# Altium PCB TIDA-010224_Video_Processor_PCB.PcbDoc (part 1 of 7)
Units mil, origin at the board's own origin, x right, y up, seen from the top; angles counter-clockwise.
Board outline 2355.46 x 4164 mil, 10 copper layers (L1-Top Layer, L2-GND, L3-SIG1, L4-GND, L5-PWR, L6-PWR, L7-GND, L8-SIG2, L9-GND, L10-Bottom Layer), stack 62.2 mil thick; 508 components, 274 nets, 3619 pads, 705 vias.
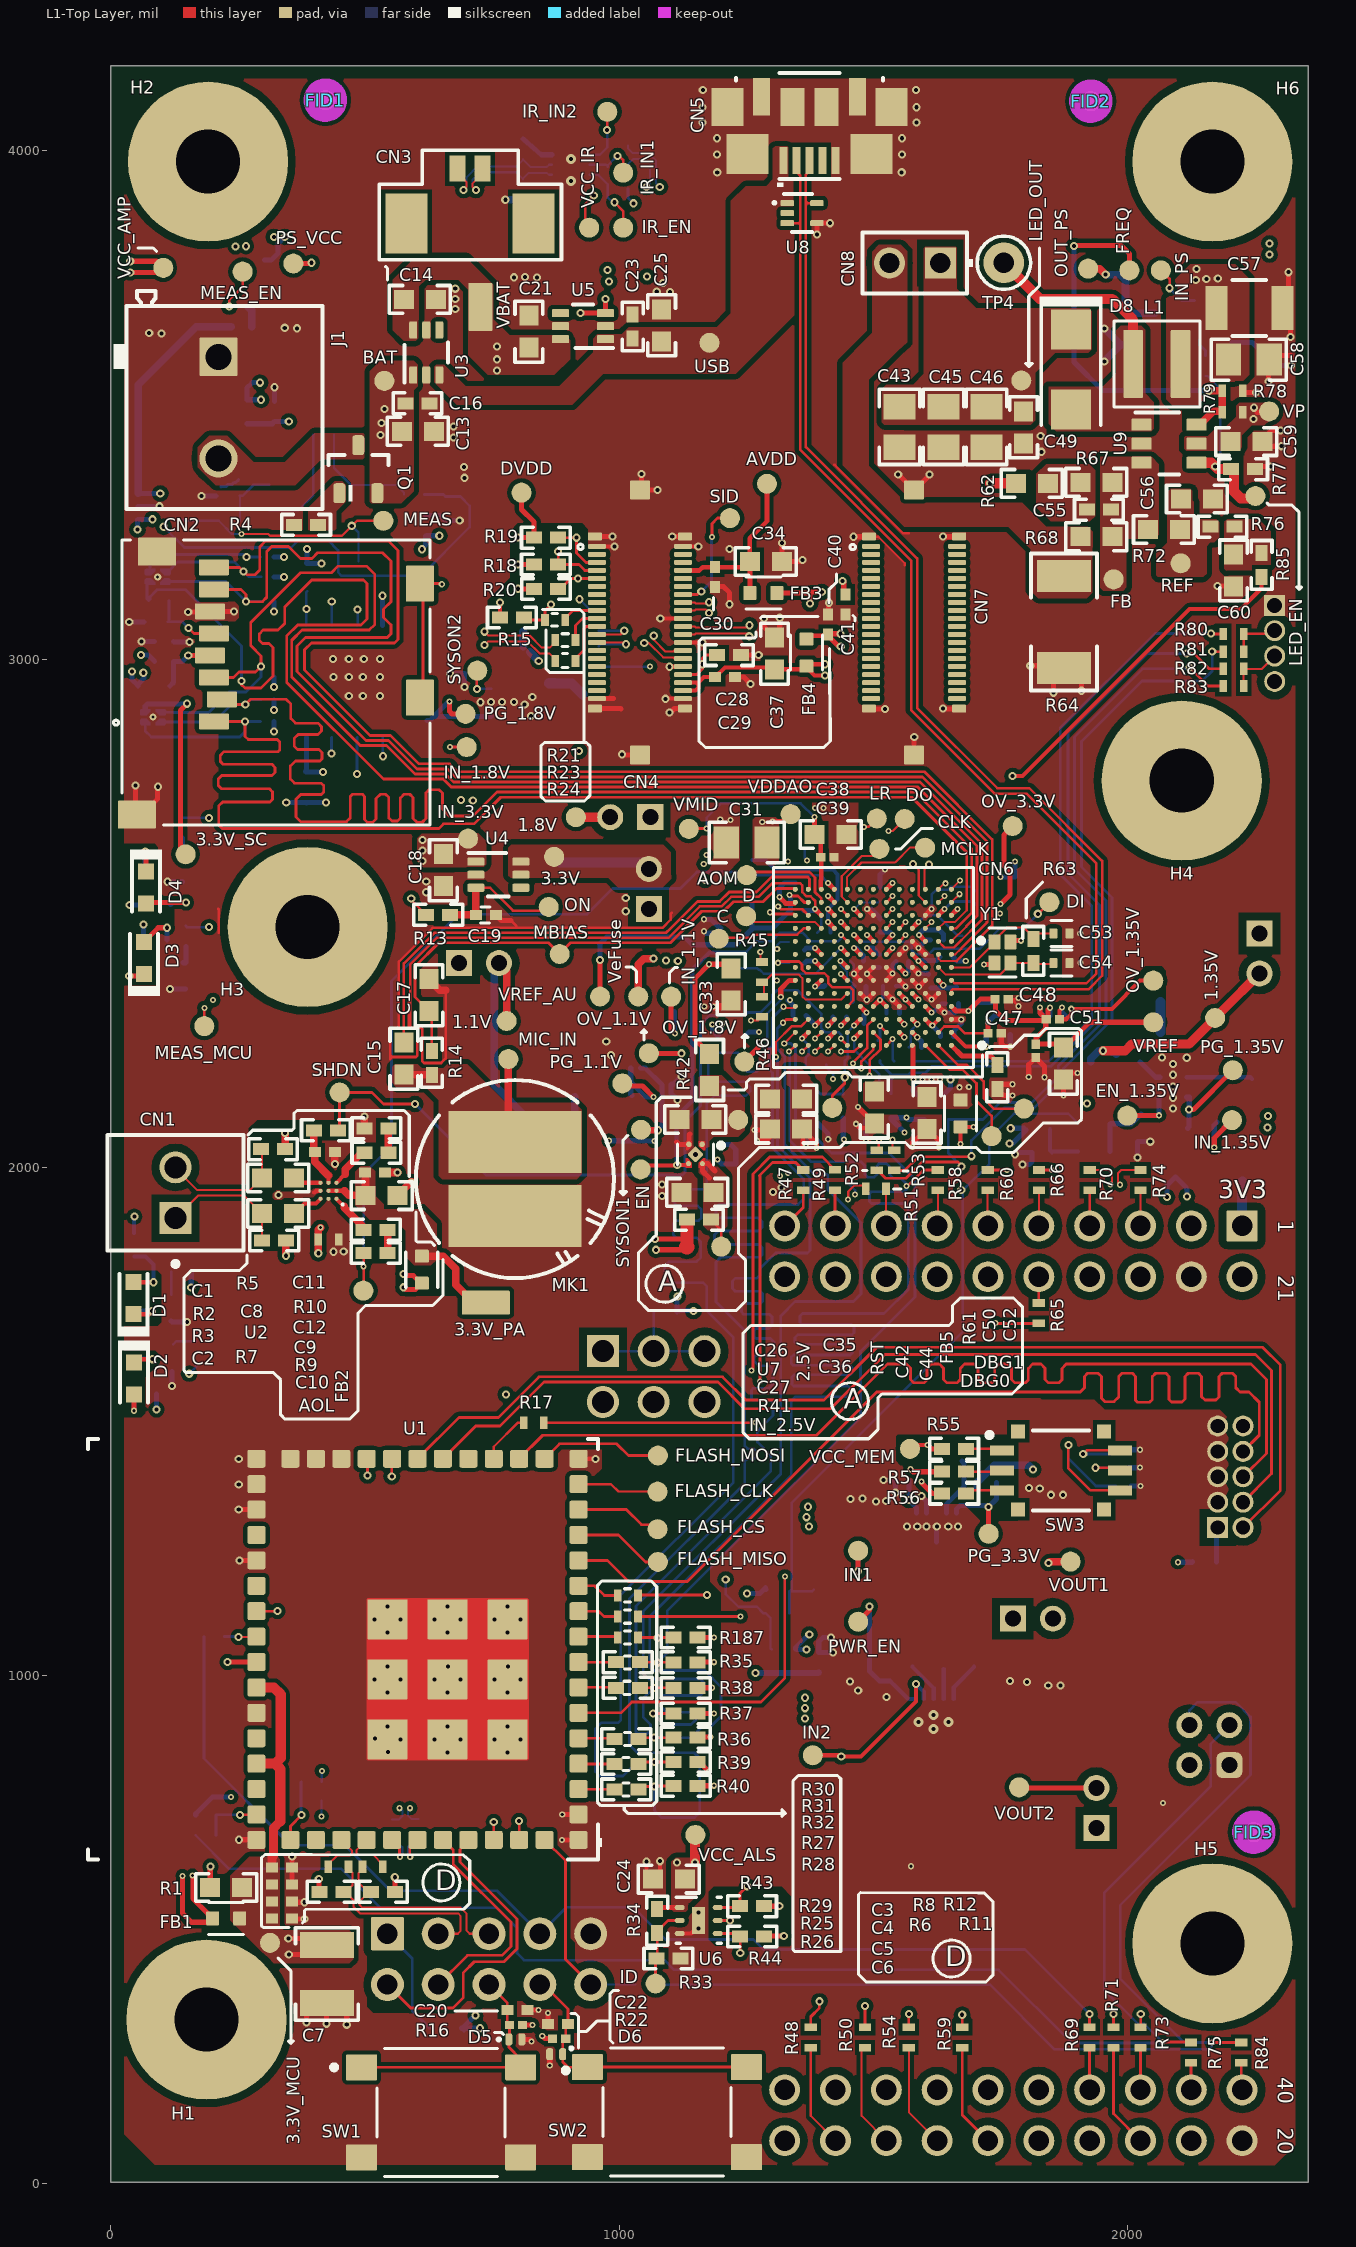
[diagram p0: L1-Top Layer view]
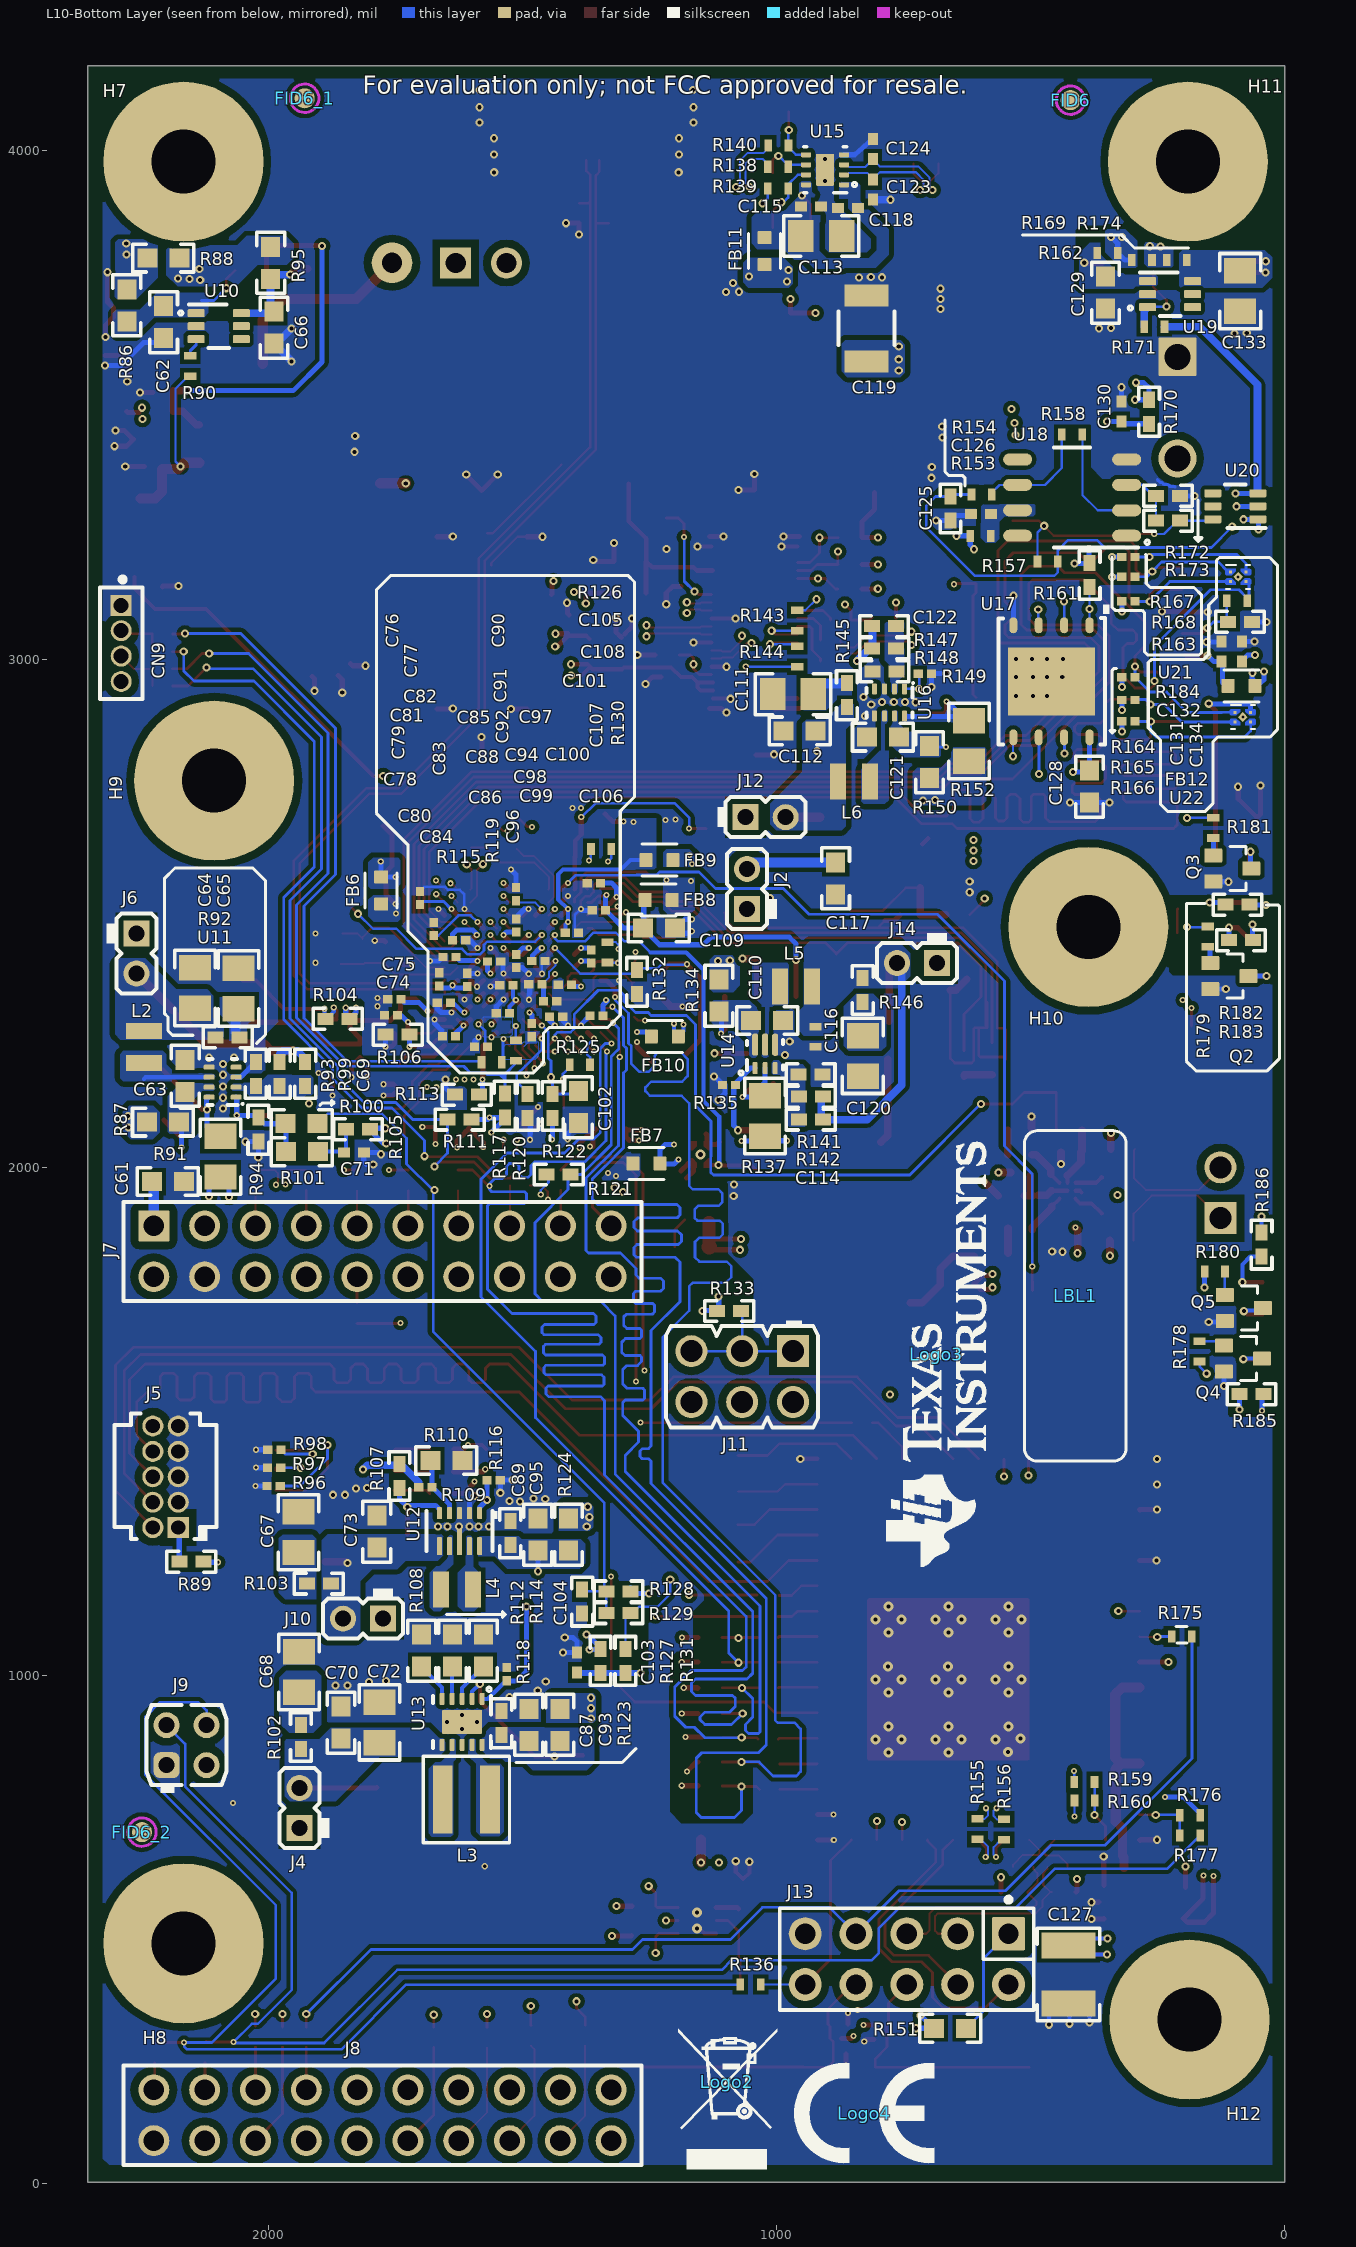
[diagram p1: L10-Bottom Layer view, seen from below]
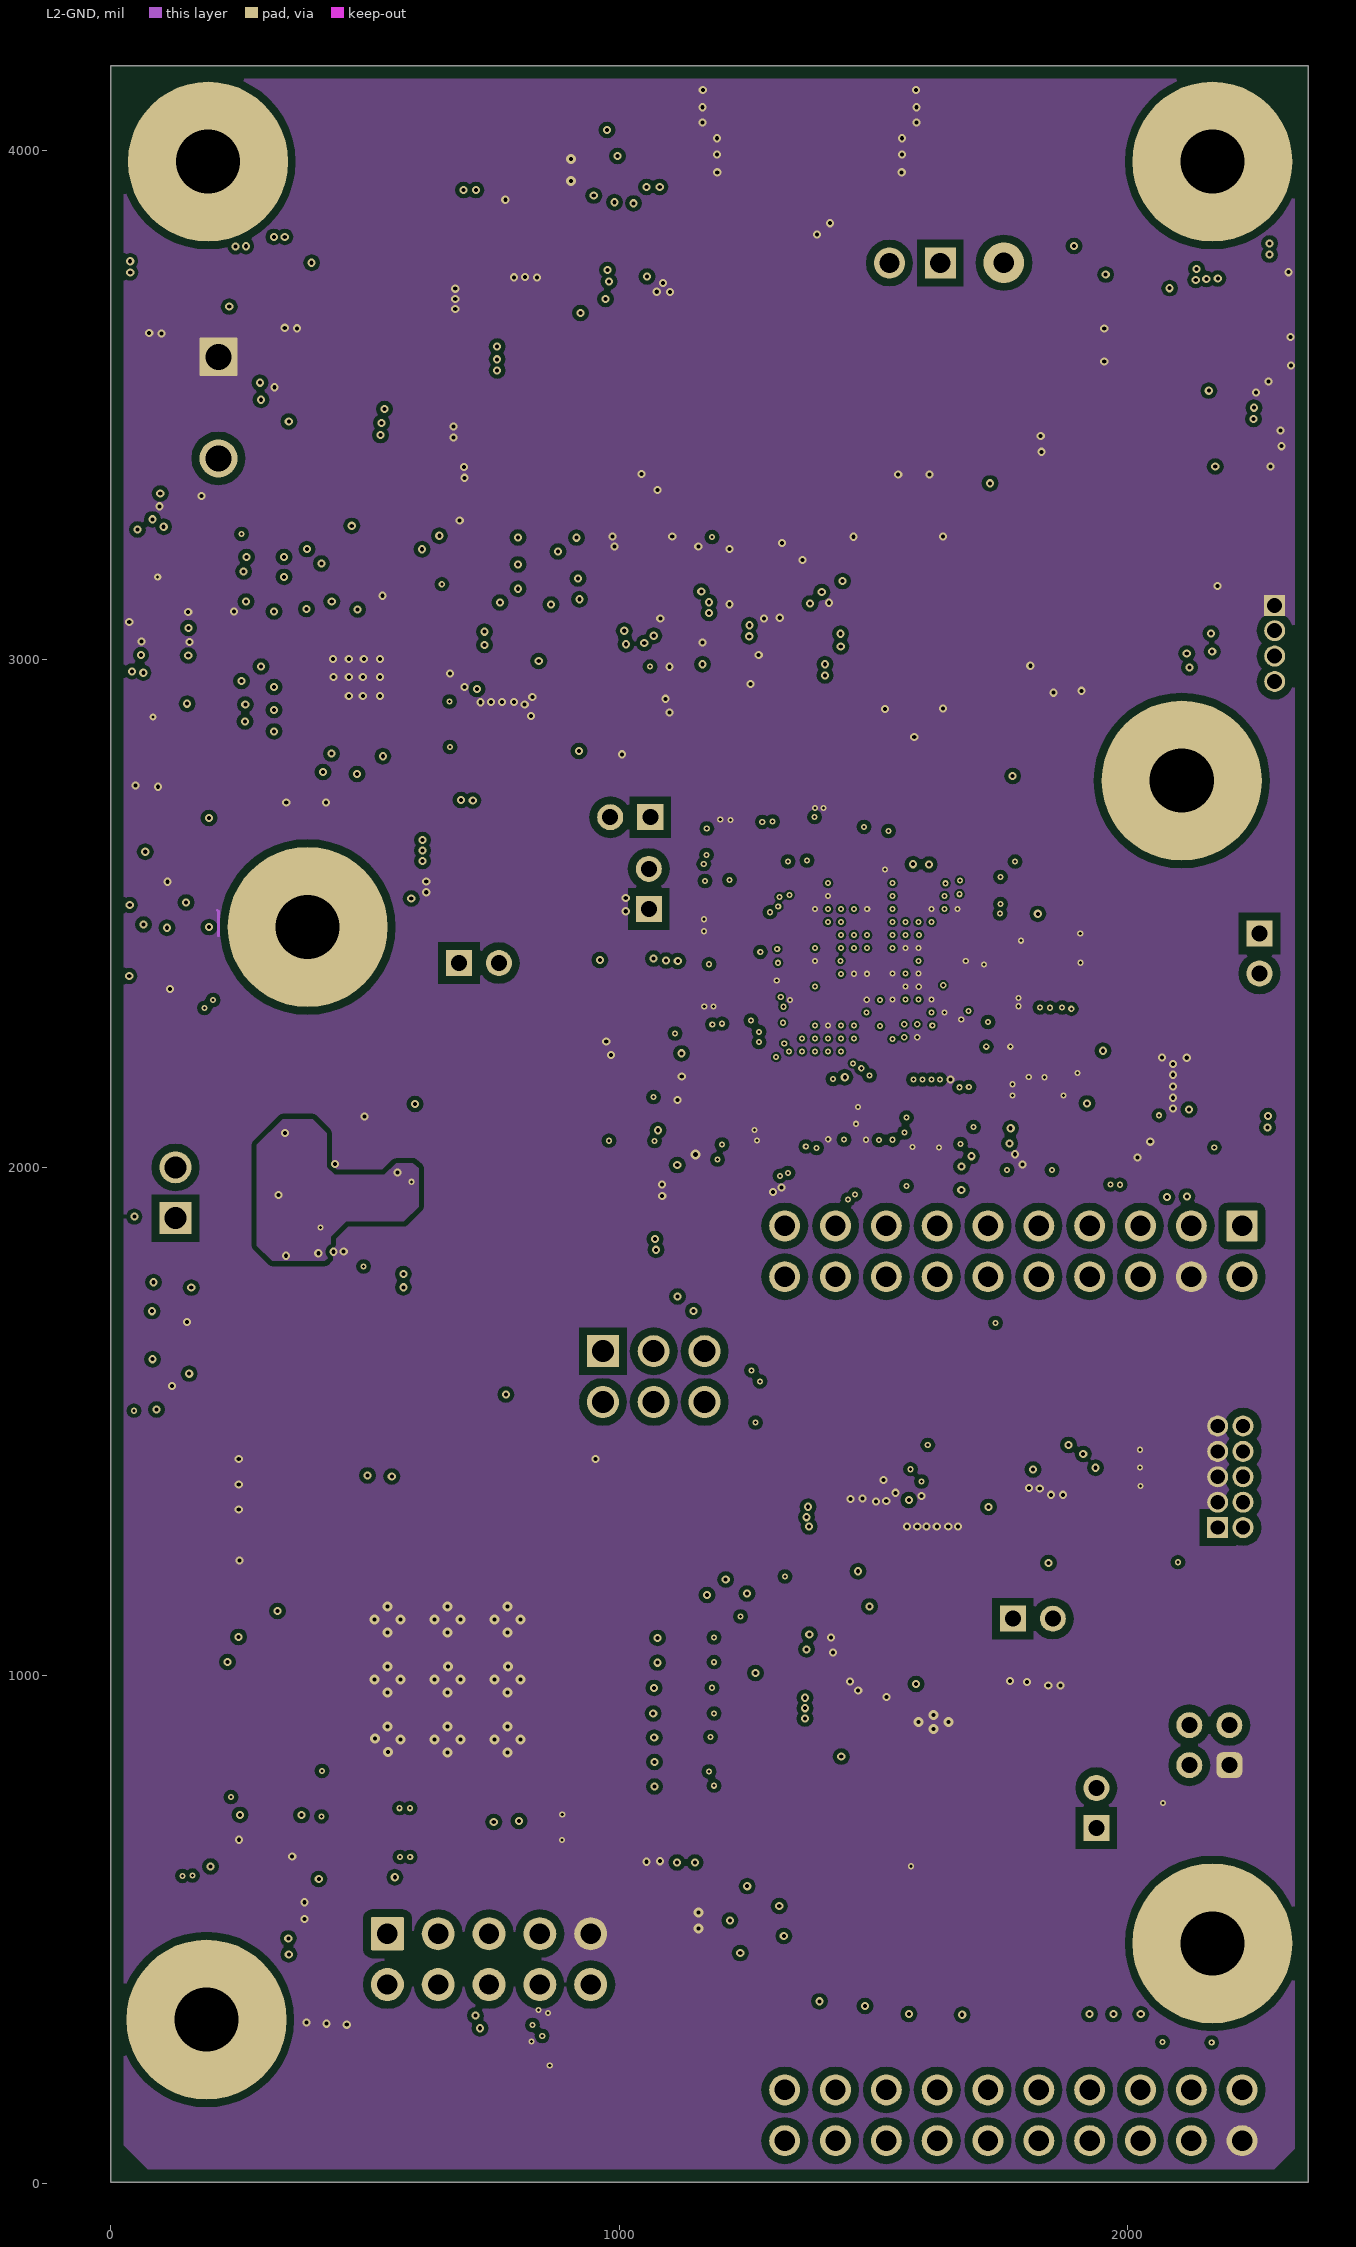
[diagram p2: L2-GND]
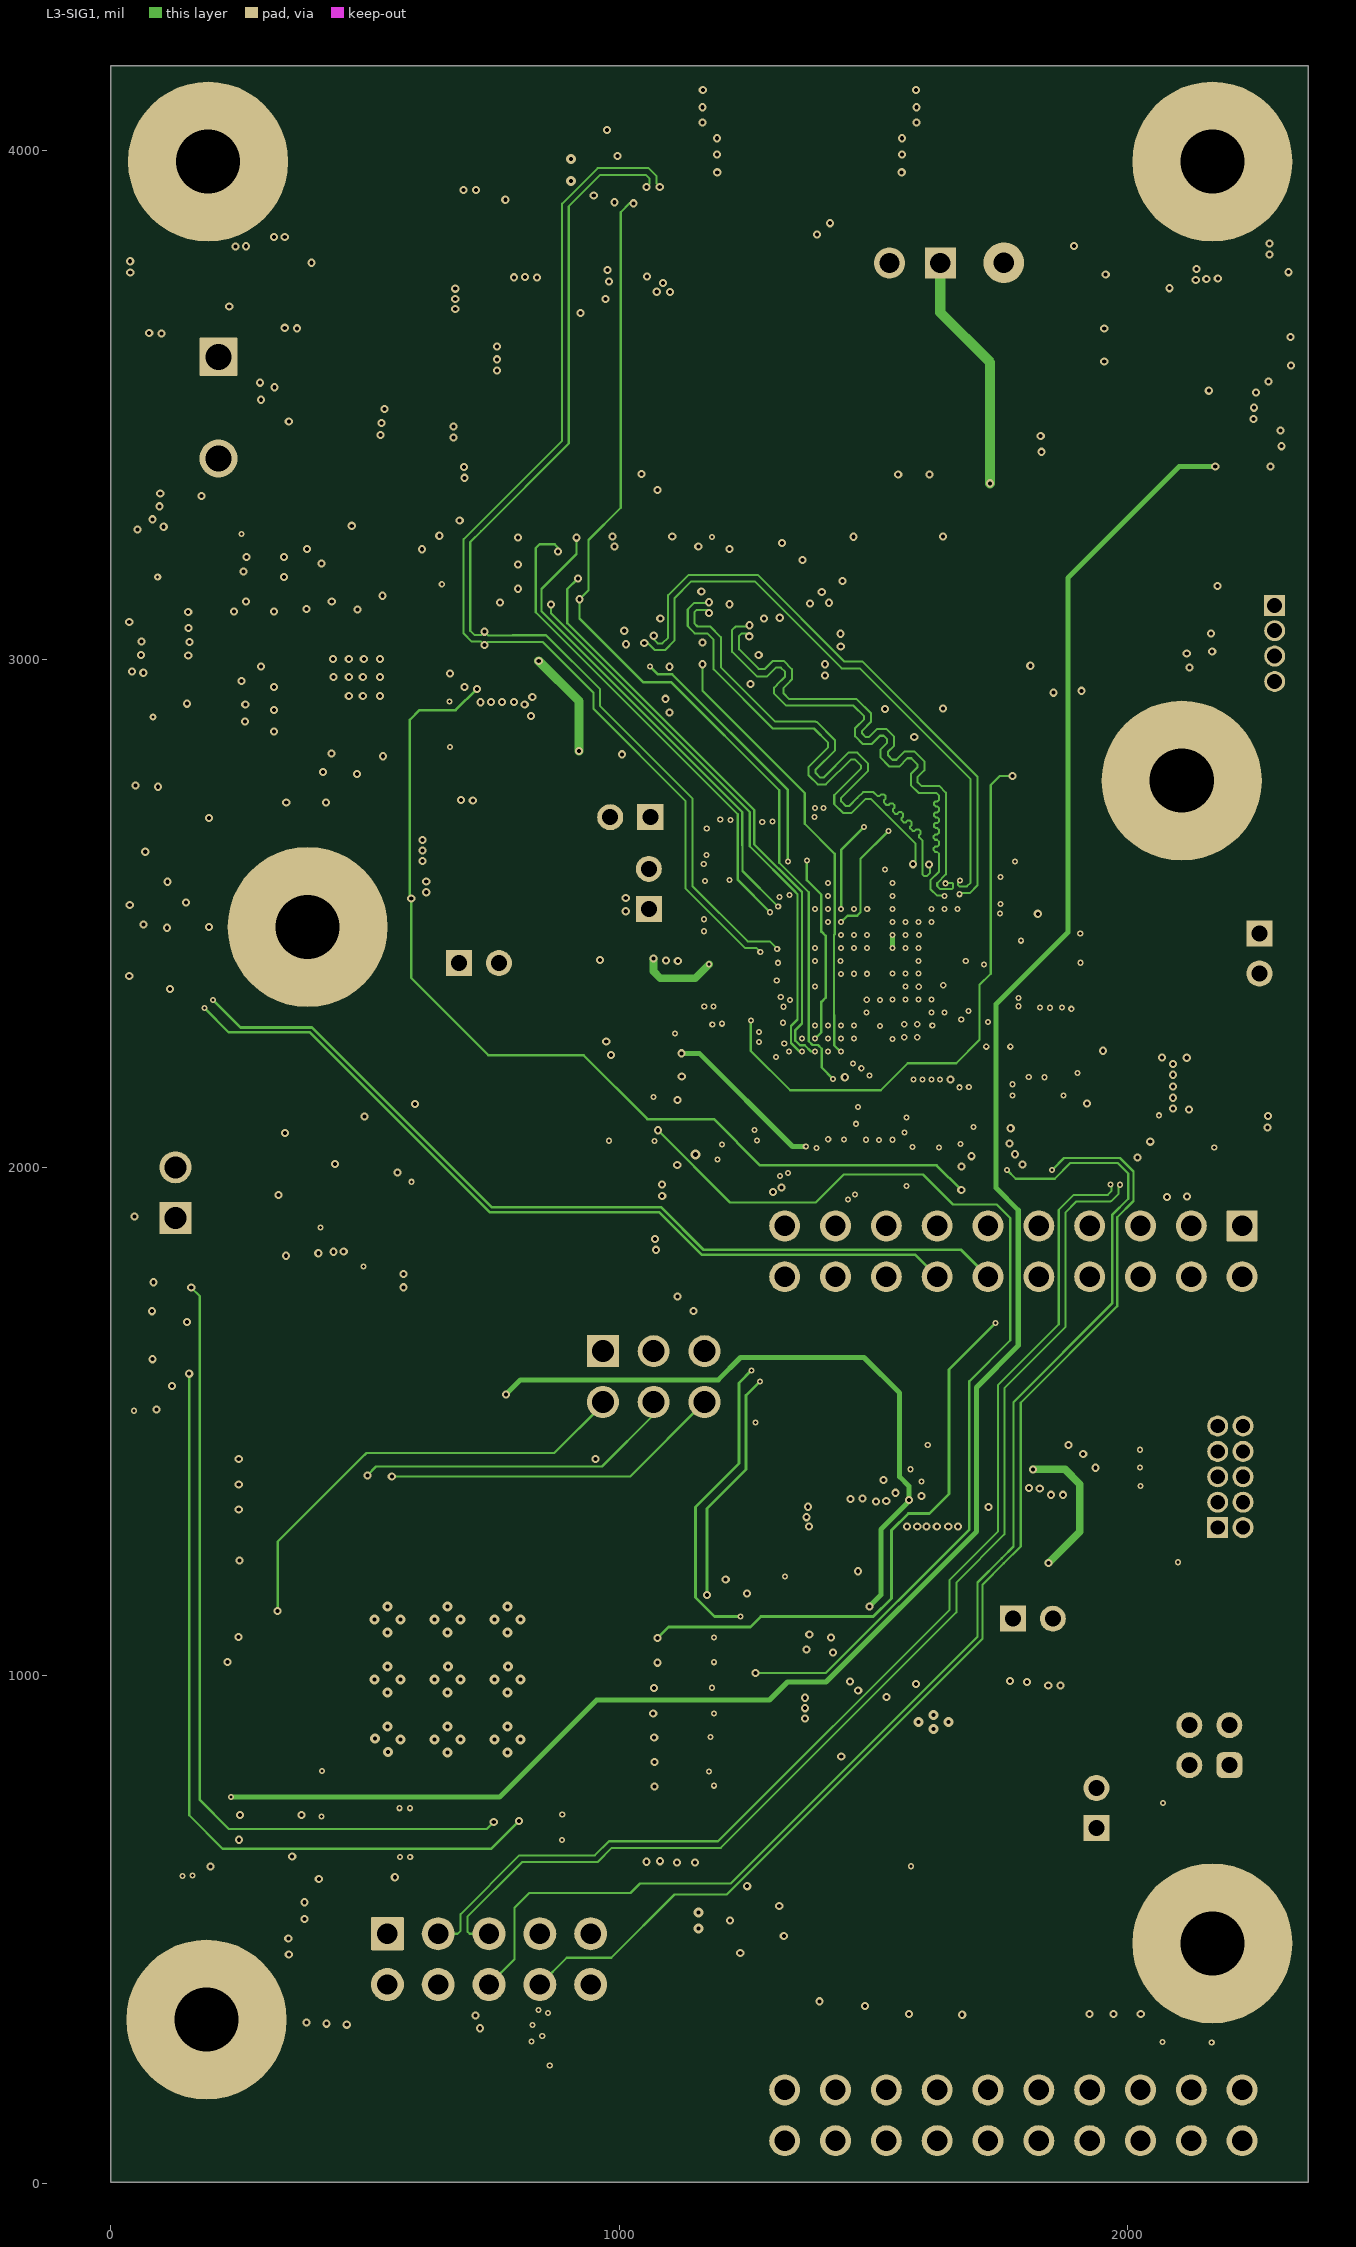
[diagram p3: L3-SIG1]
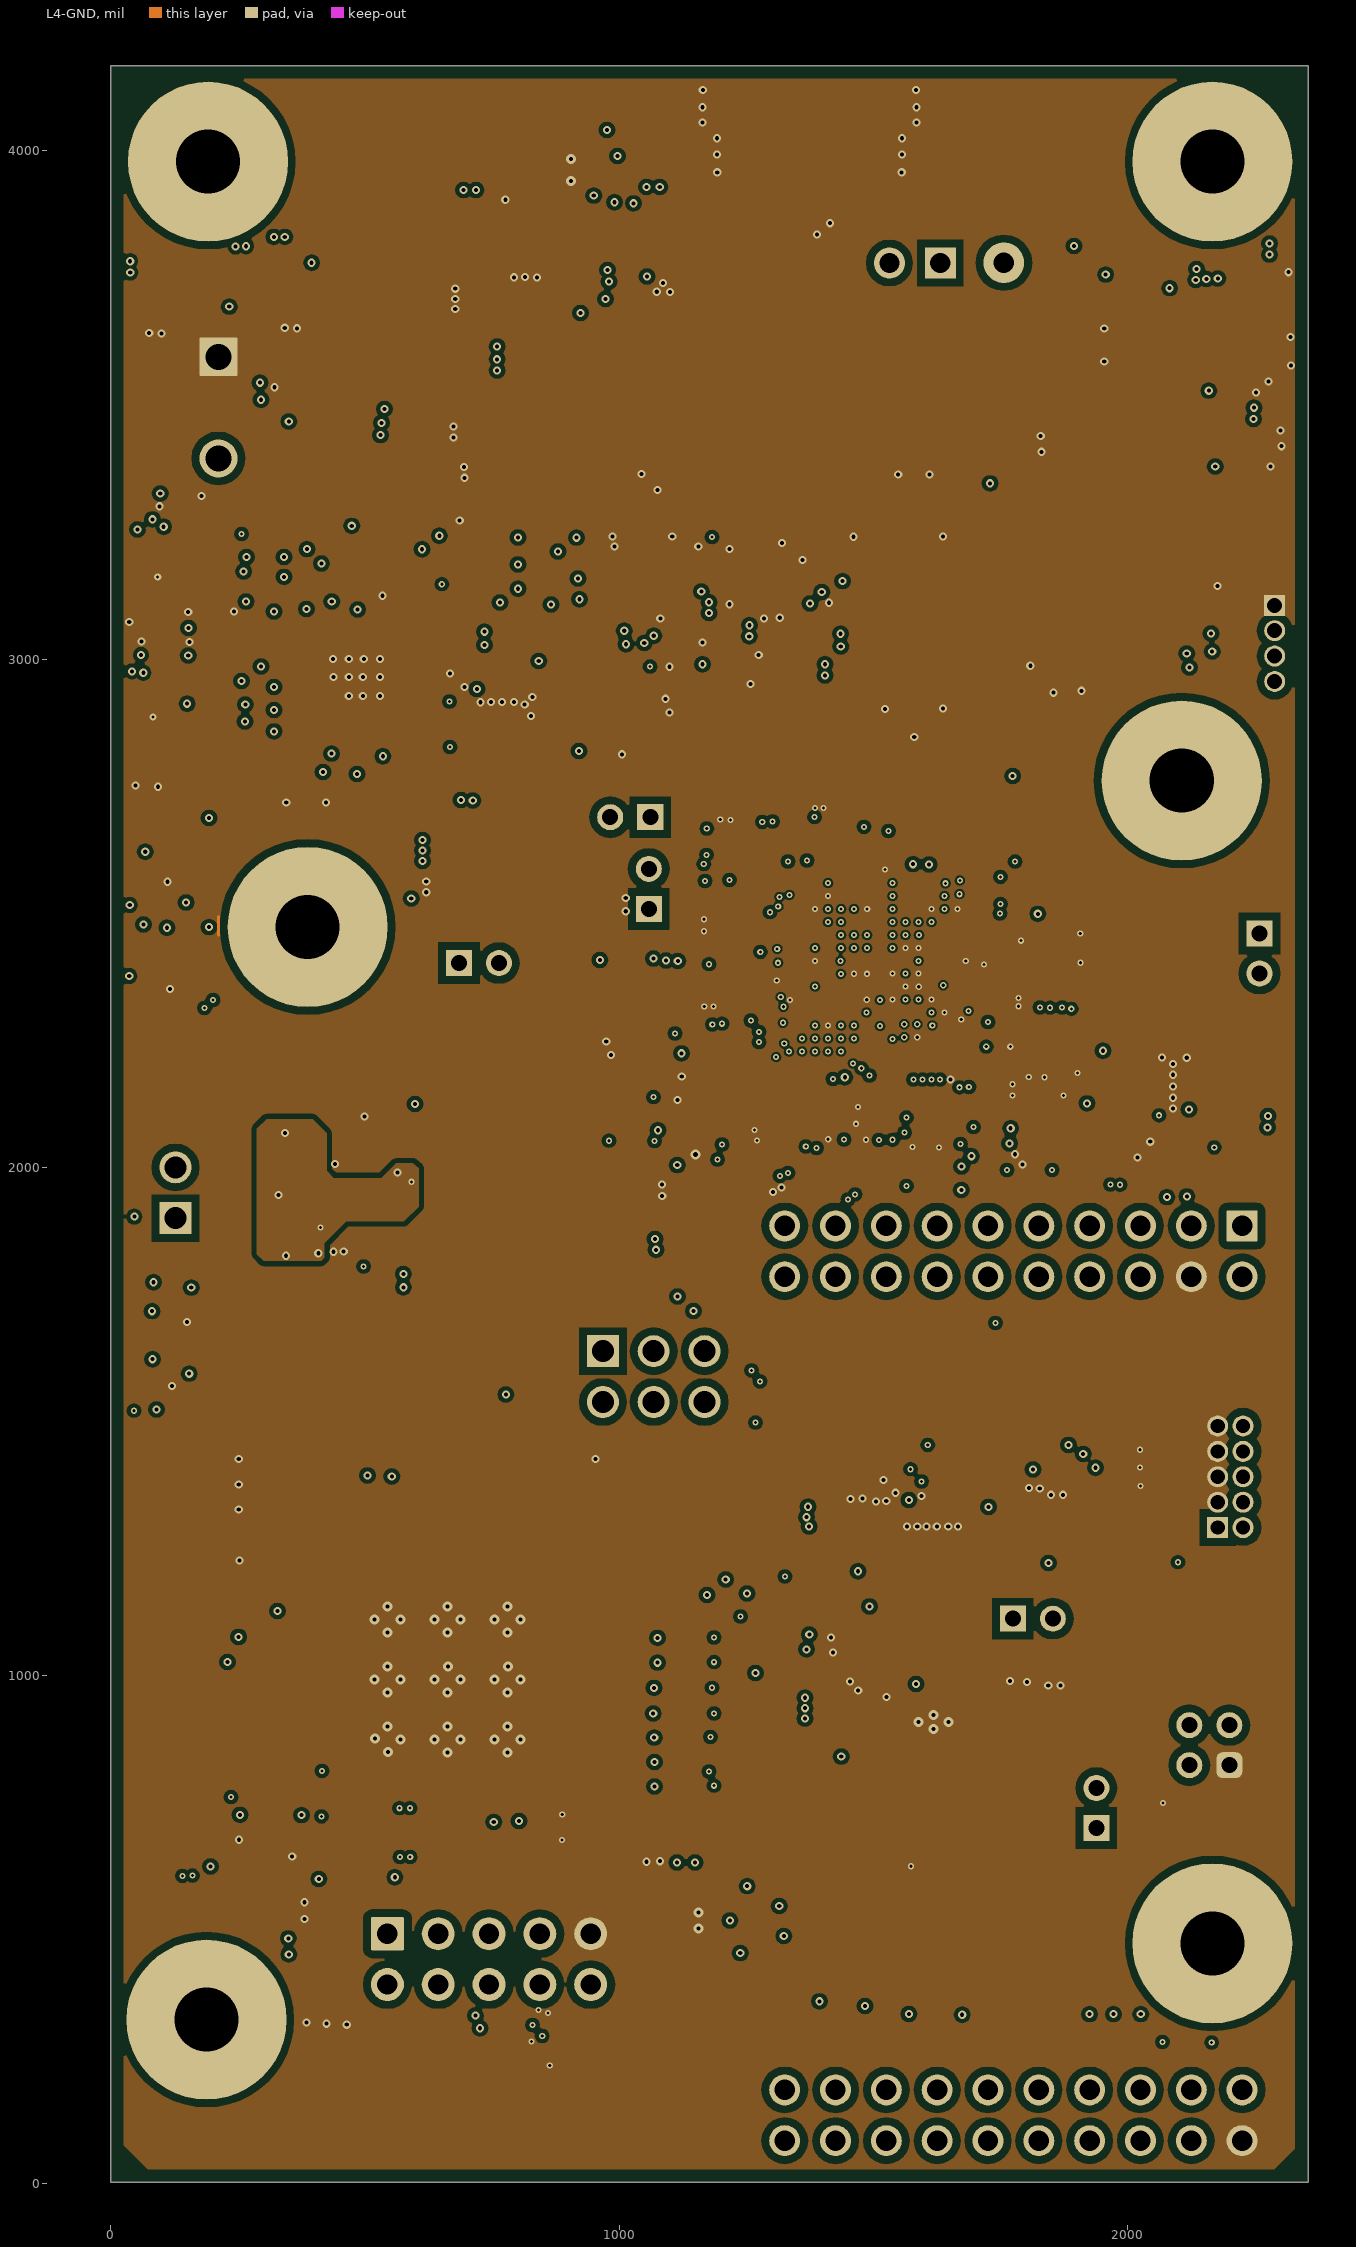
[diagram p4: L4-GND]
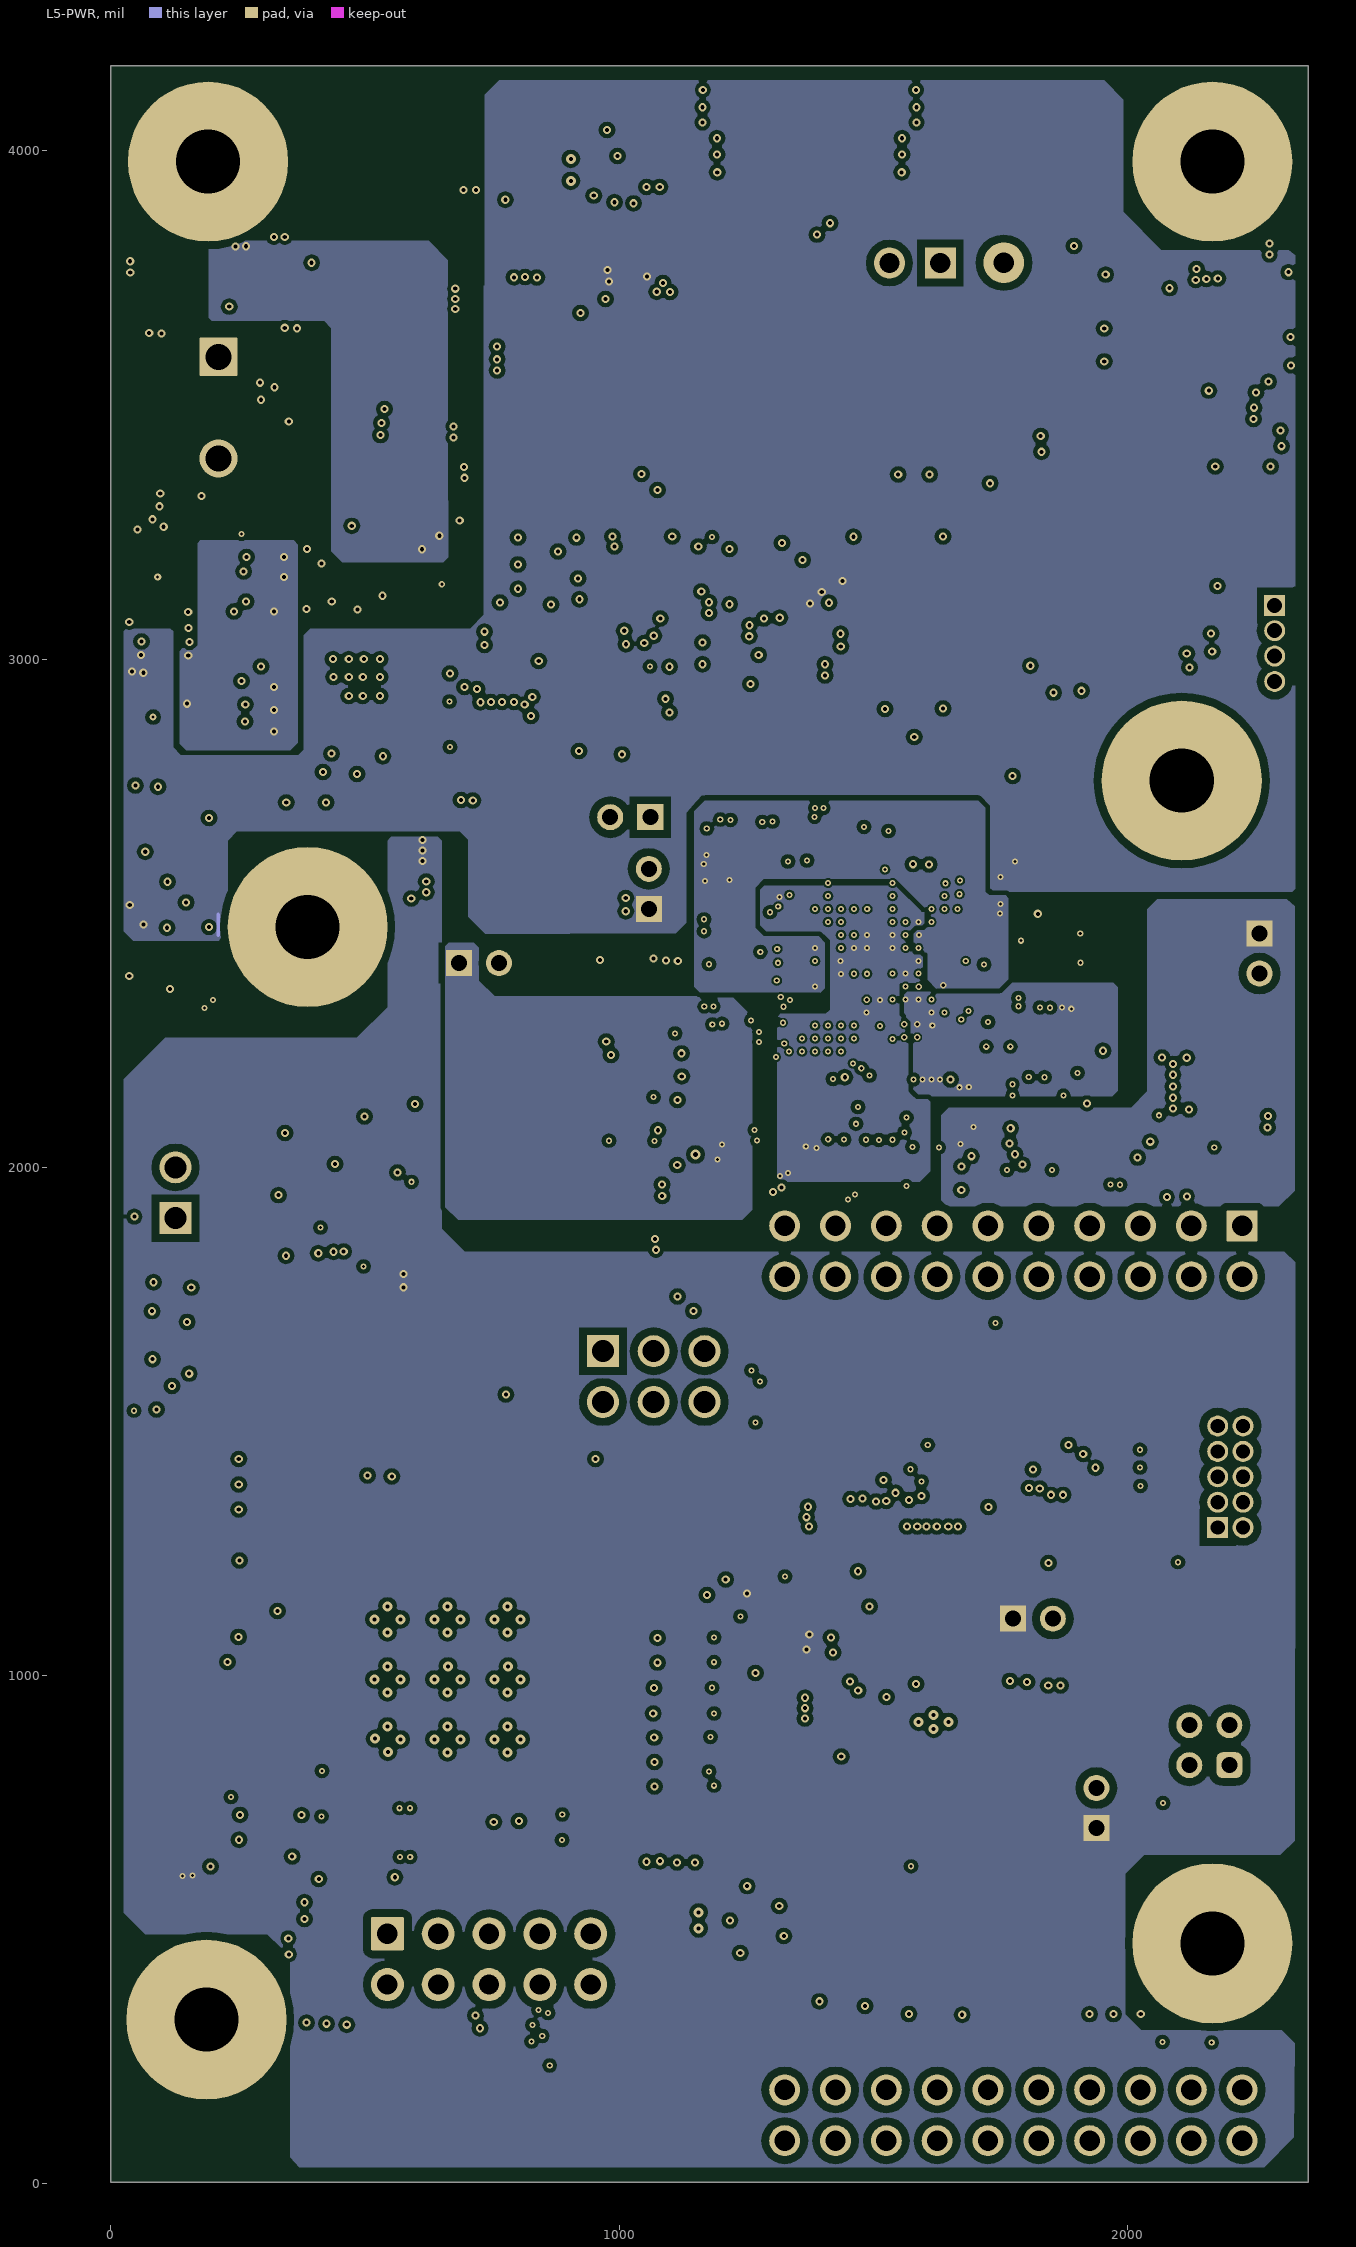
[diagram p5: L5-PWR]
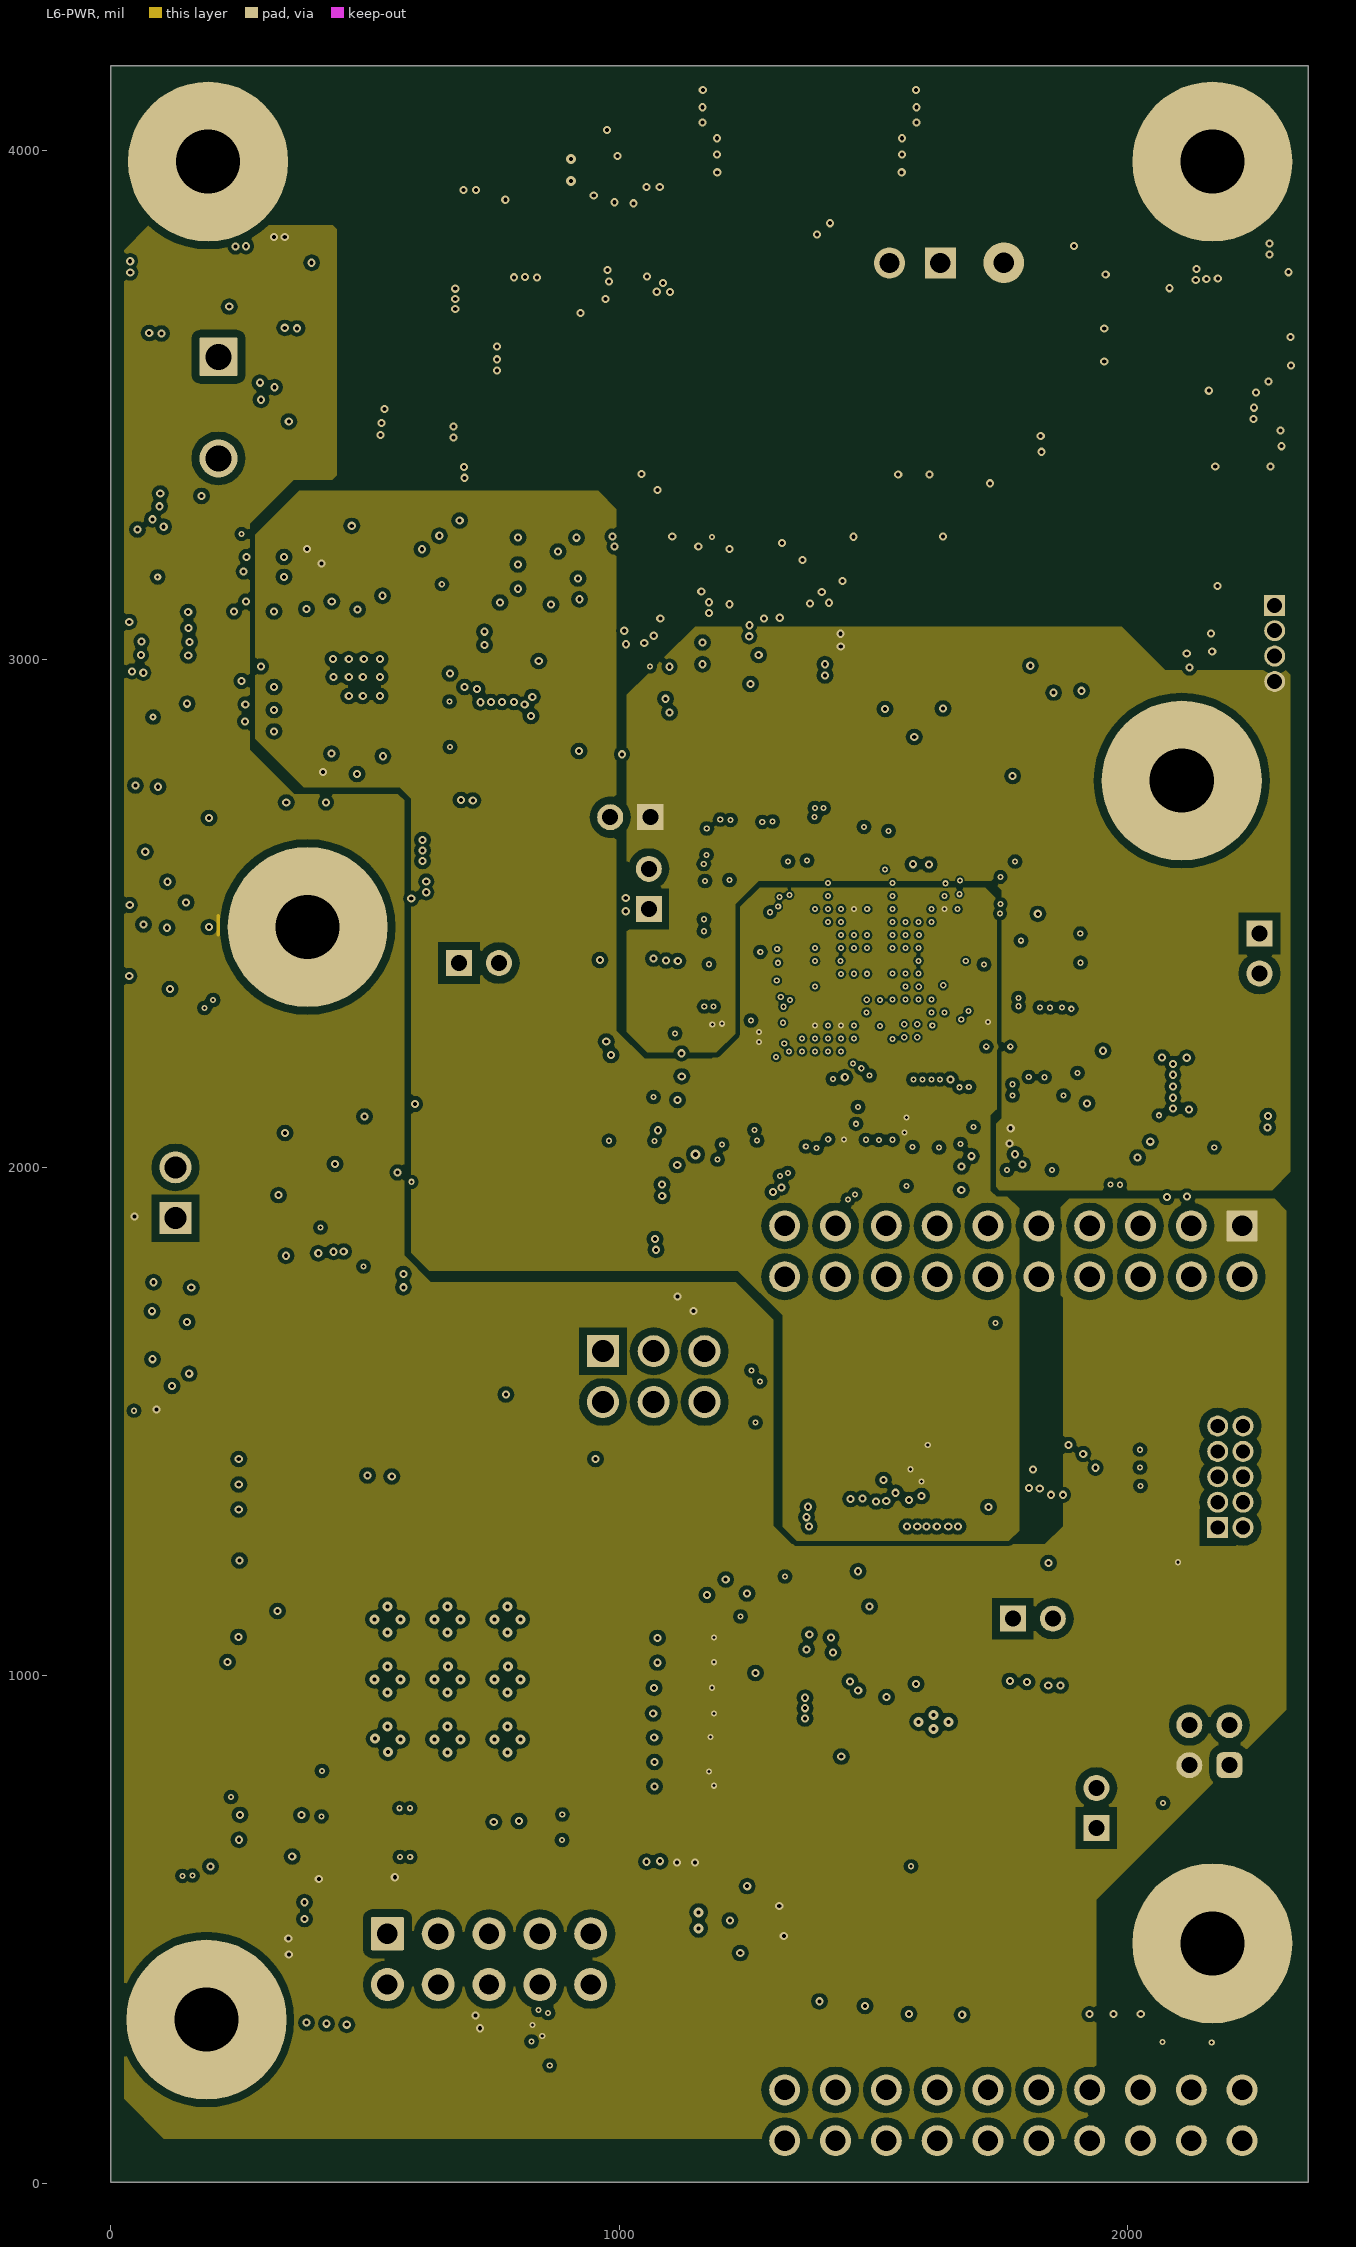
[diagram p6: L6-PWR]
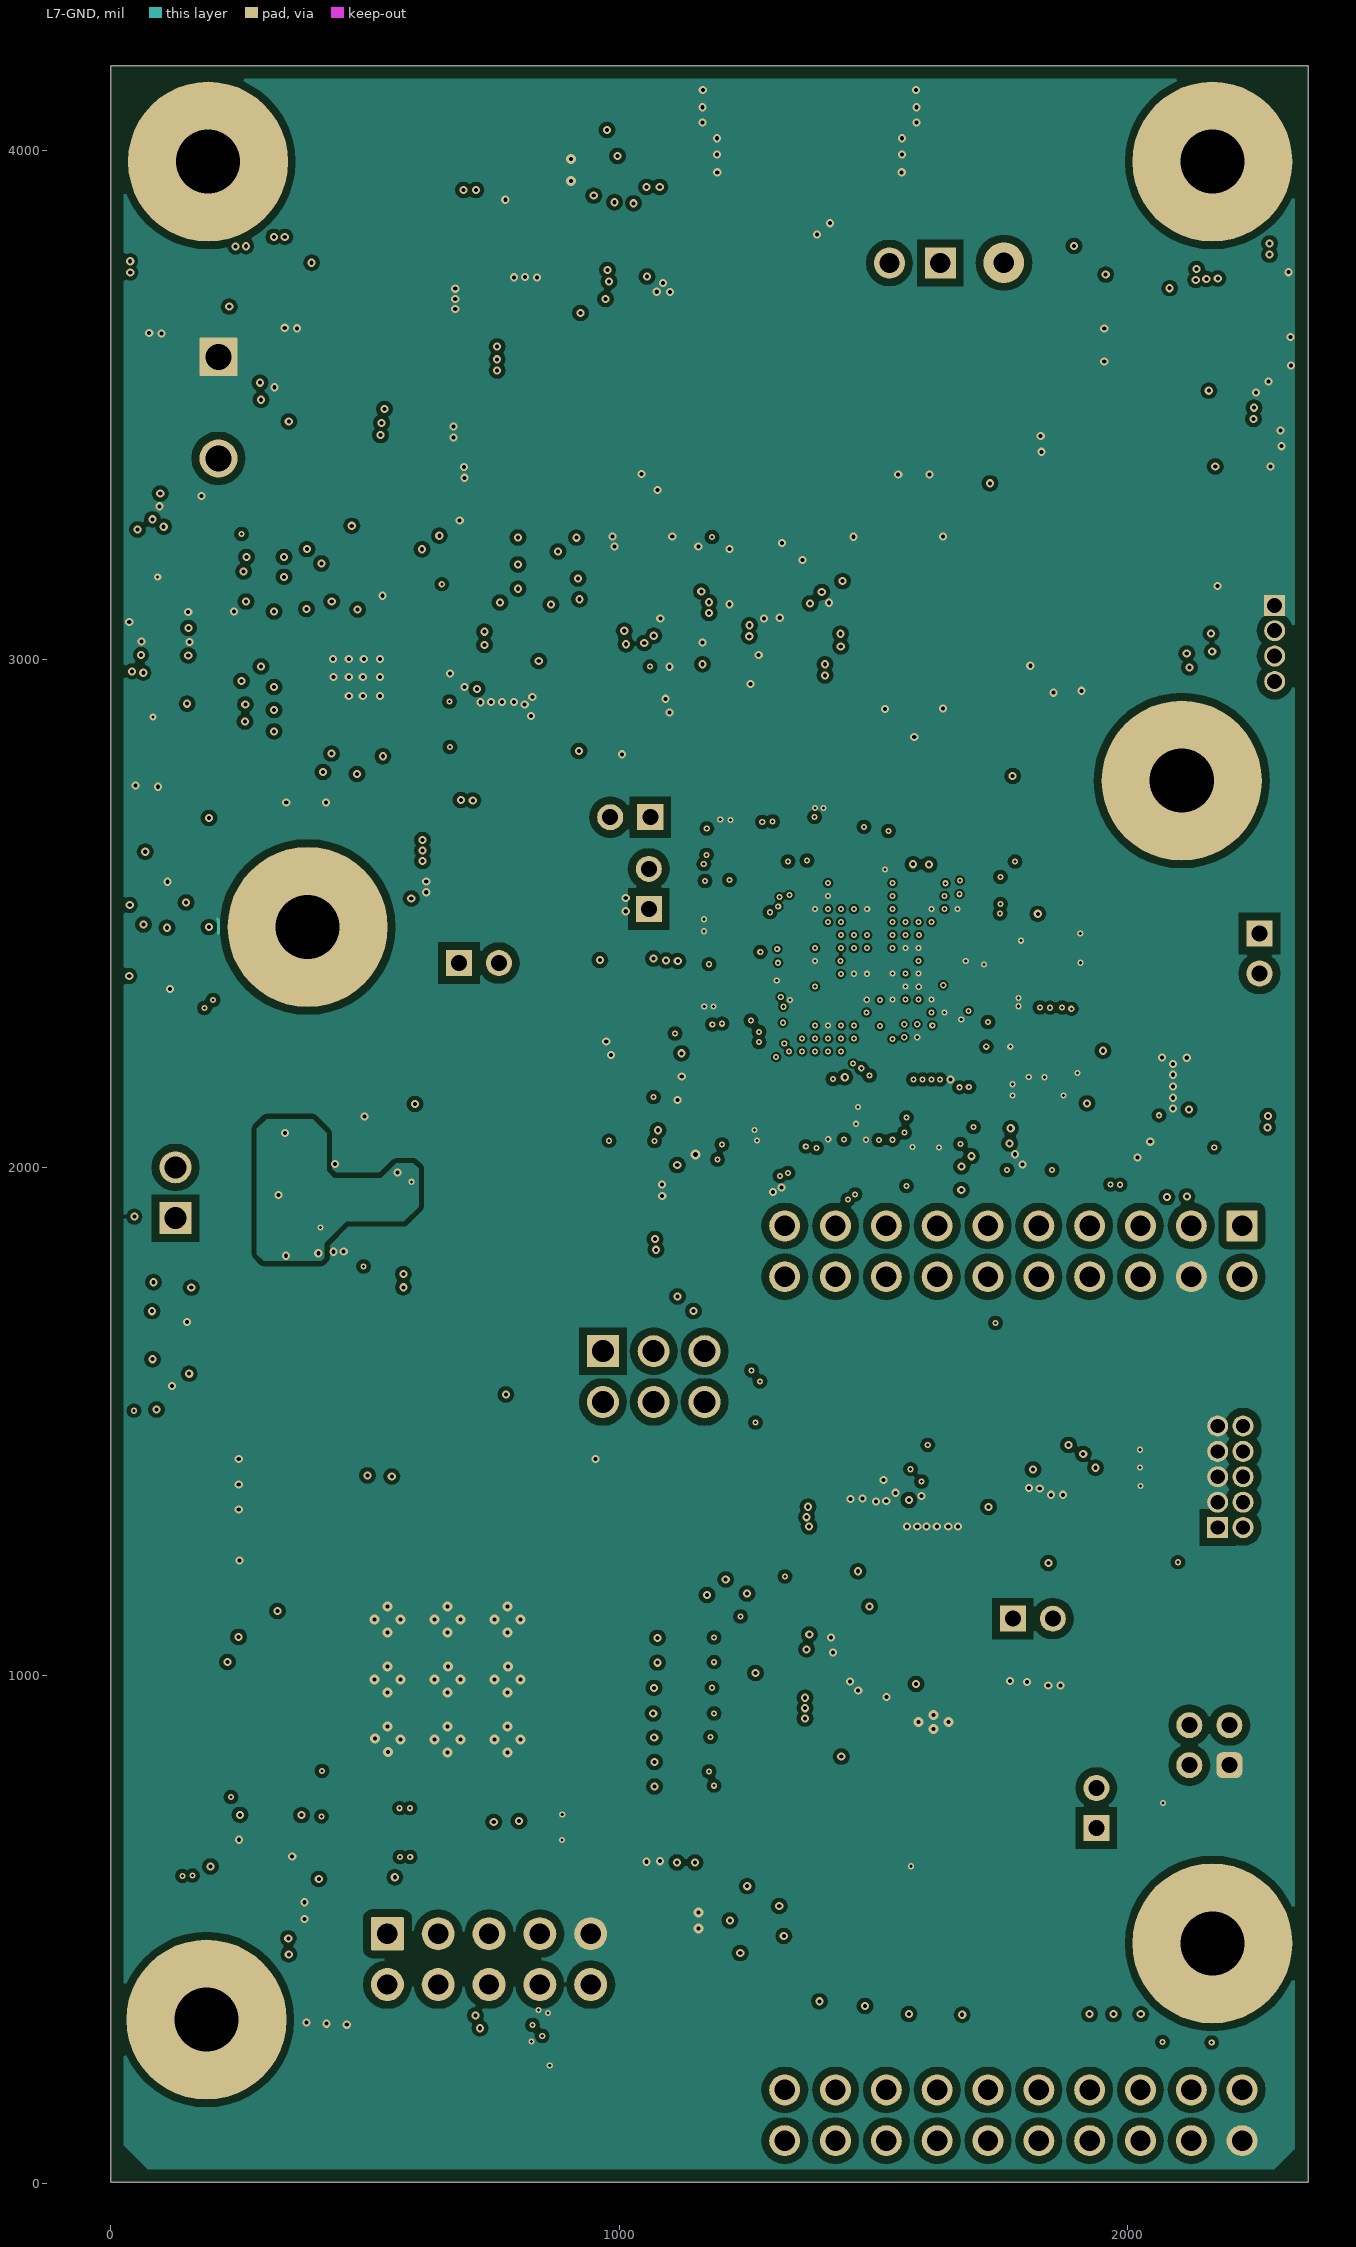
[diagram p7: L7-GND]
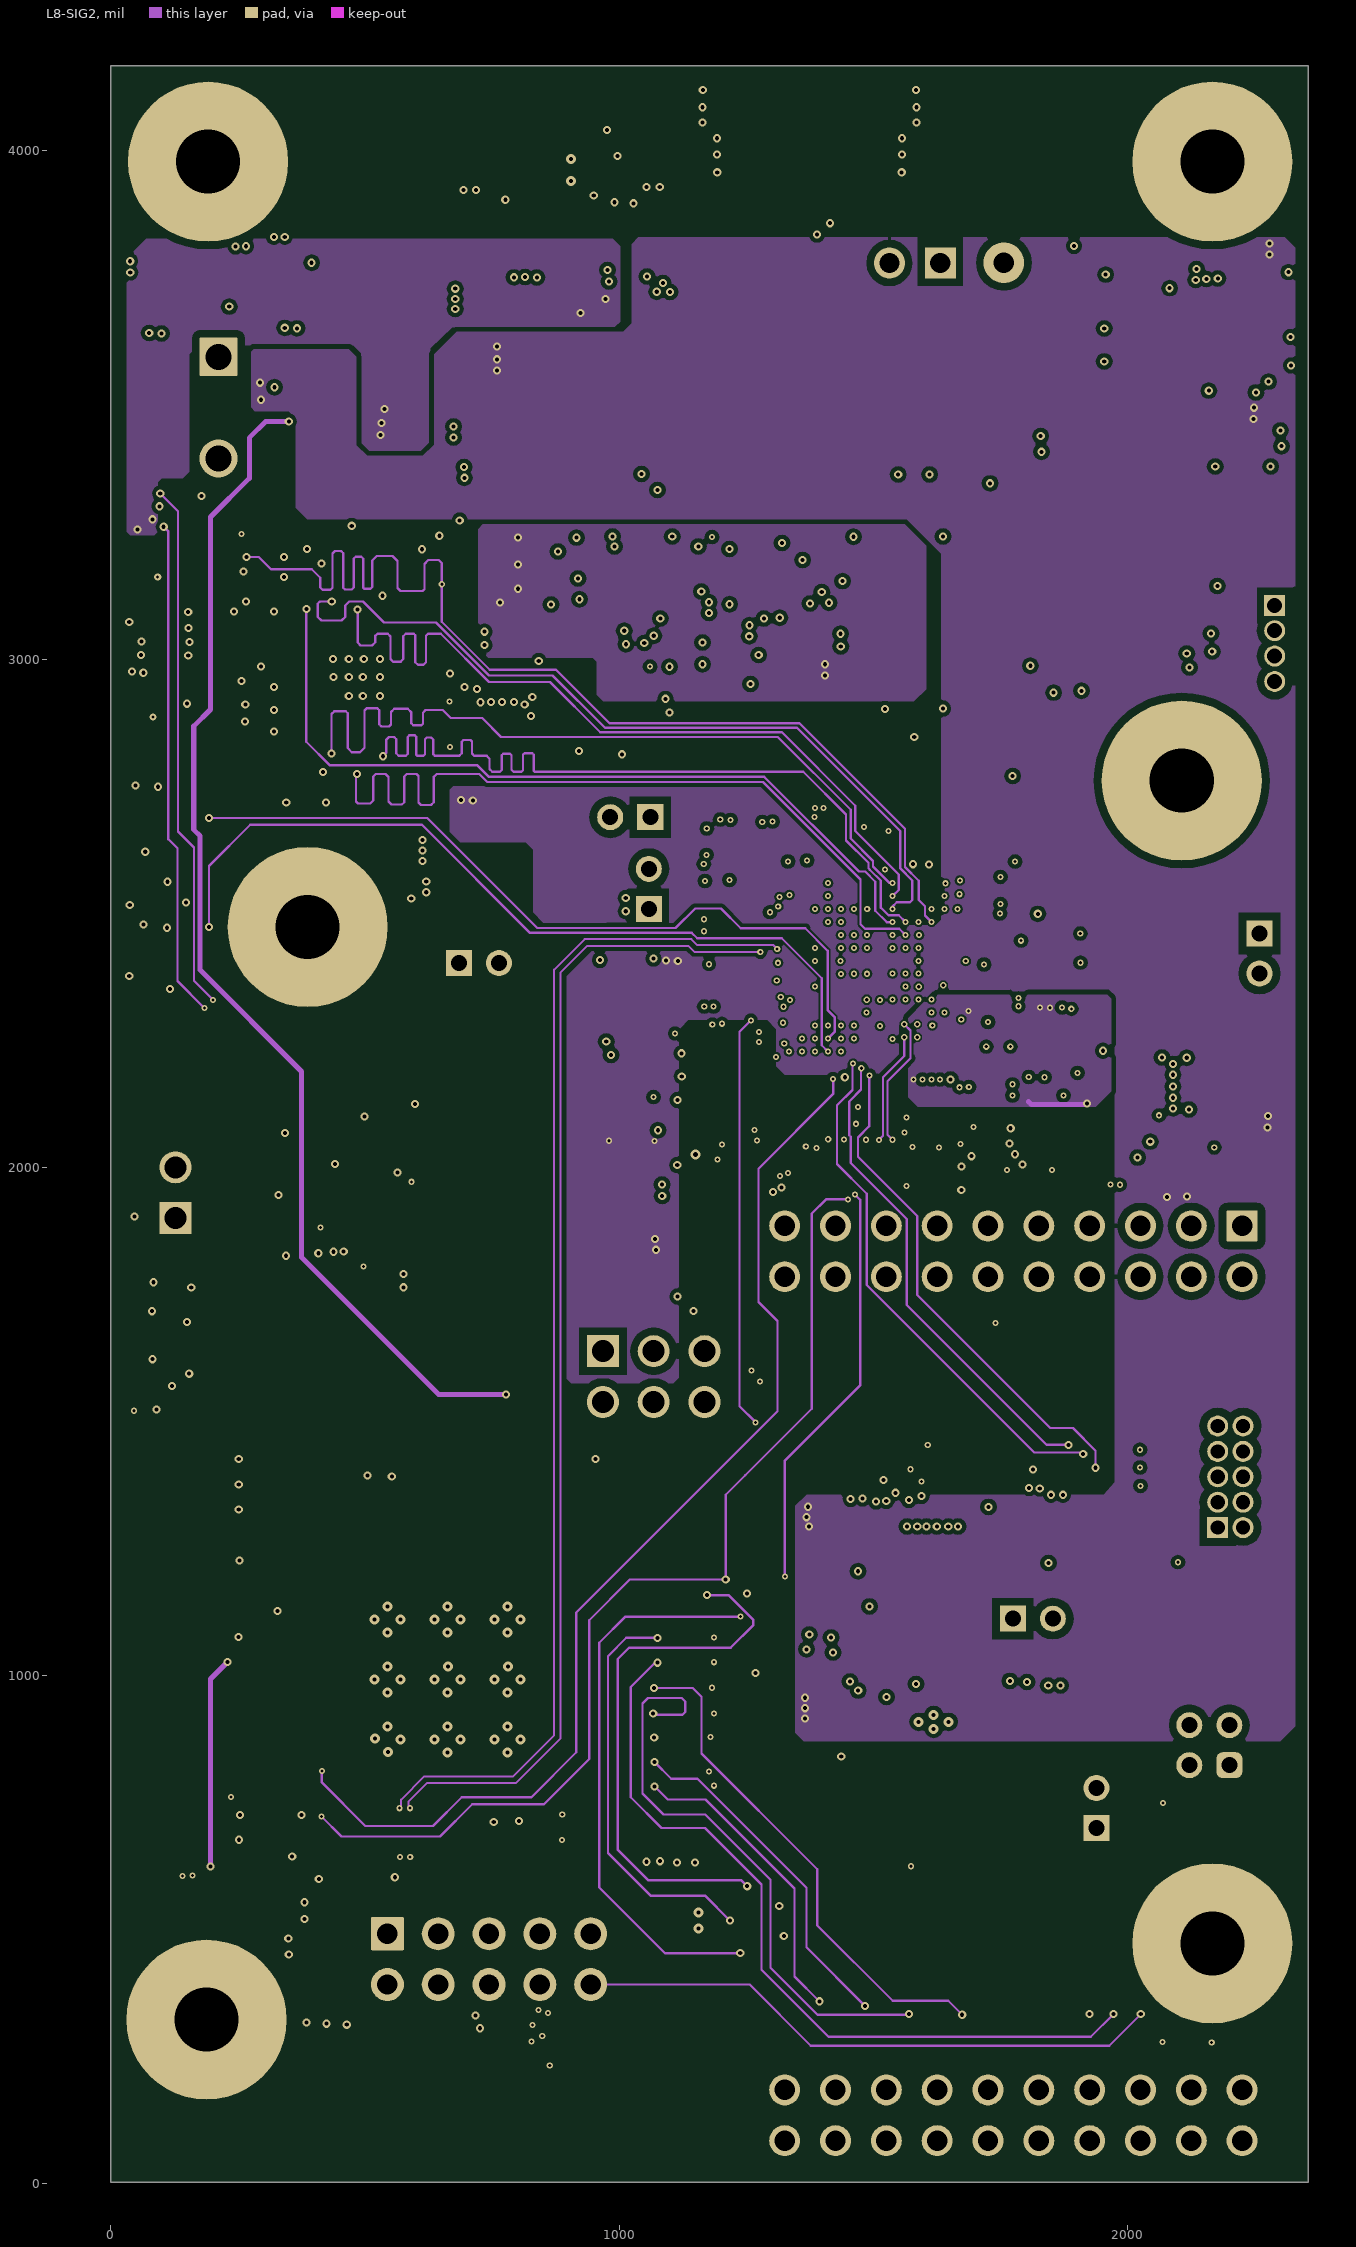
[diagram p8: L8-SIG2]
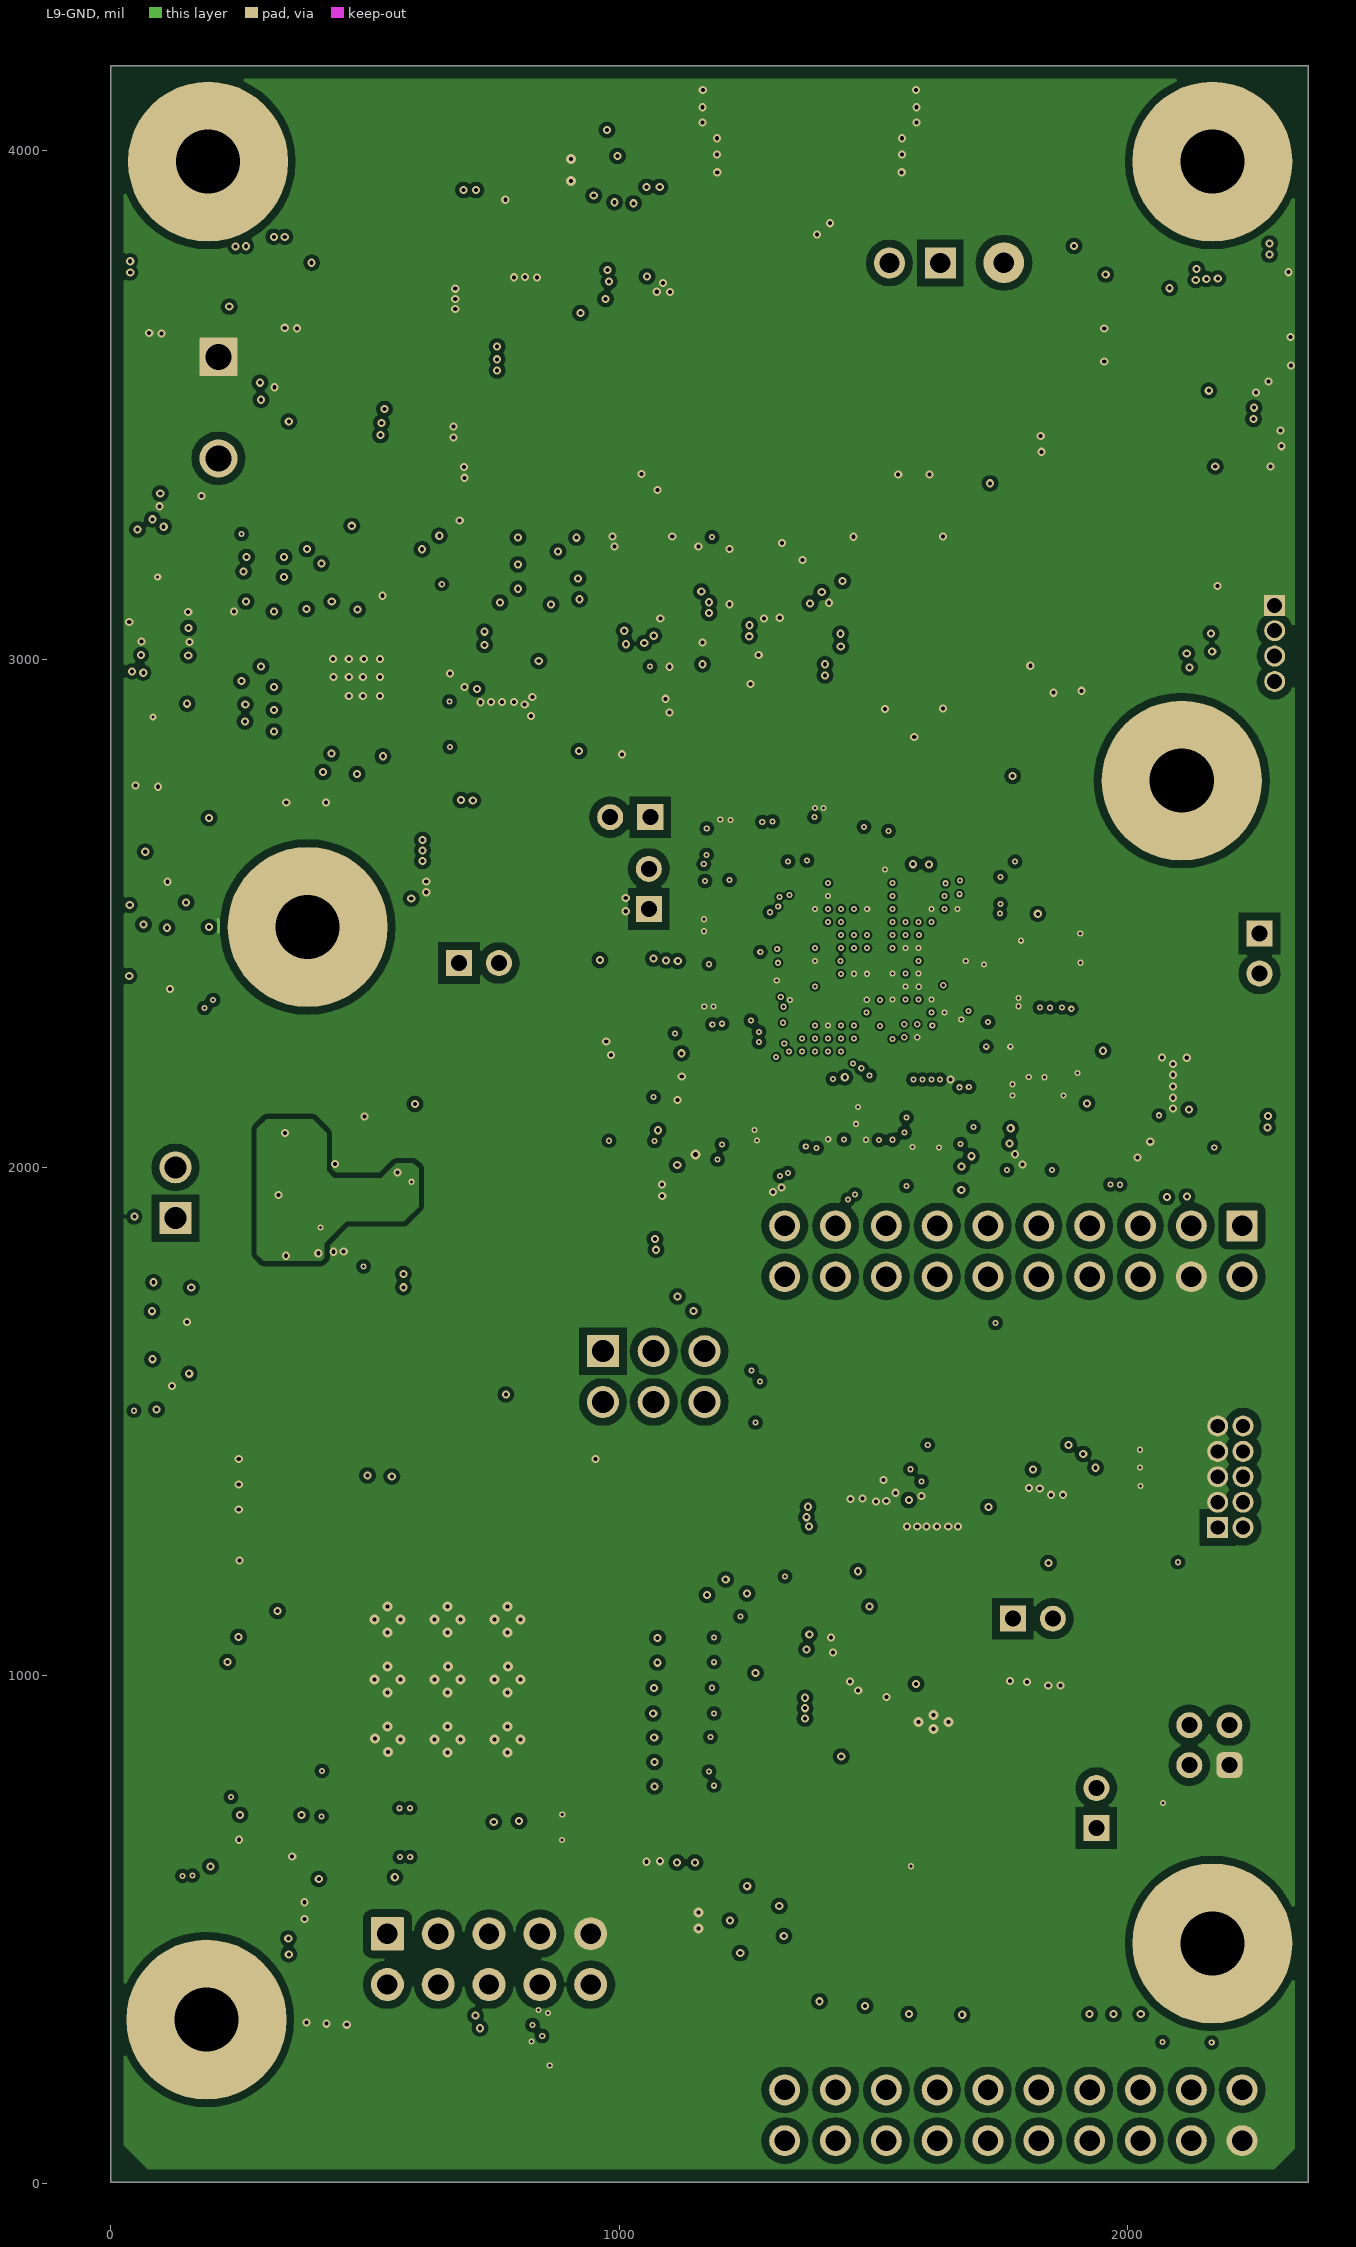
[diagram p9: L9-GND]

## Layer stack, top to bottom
Top Solder: solder mask 0.4, Solder Resist, Dk 3.5
L1-Top Layer: signal copper 1.76
Dielectric 2: dielectric 3.94, FR-4 High Tg, Dk 4.2
L2-GND: signal copper 1.18
Dielectric1: core 5.91, FR-4 High Tg, Dk 4.8
L3-SIG1: signal copper 1.18
Dielectric 3: dielectric 6.89, FR-4 High Tg, Dk 4.2
L4-GND: signal copper 1.18
Dielectric 4: dielectric 5.91, FR-4 High Tg, Dk 4.2
L5-PWR: signal copper 1.18
Dielectric 5: dielectric 3.94, FR-4 High Tg, Dk 4.2
L6-PWR: signal copper 1.18
Dielectric 6: dielectric 5.91, FR-4 High Tg, Dk 4.2
L7-GND: signal copper 1.18
Dielectric 7: dielectric 6.89, FR-4 High Tg, Dk 4.2
L8-SIG2: signal copper 1.18
Dielectric 8: dielectric 5.91, FR-4 High Tg, Dk 4.2
L9-GND: signal copper 1.18
Dielectric 9: dielectric 3.94, FR-4 High Tg, Dk 4.2
L10-Bottom Layer: signal copper 1.76
Bottom Solder: solder mask 0.4, Solder Resist, Dk 3.5

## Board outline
0,3.33 2355.46,3.33 2355.46,4167.33 0,4167.33

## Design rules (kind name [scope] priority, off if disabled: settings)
AcuteAngle [All] p1: minimum=4.50000000000000E+0001 checktracksonly=FALSE
AssemblyTestPointUsage [All] p1: valid=2
BoardOutlineClearance BoardOutlineClearance_MountingHoles [OnCopper and InComponentClass('Mounting Holes')] p1: gap=30 ignorepadtopadclearanceinfootprint=FALSE
BoardOutlineClearance BoardOutlineClearance_Poly [OnCopper and IsPoly] p2: gap=25 ignorepadtopadclearanceinfootprint=FALSE
BoardOutlineClearance [OnCopper and Not InComponentClass('Logo') and not InComponentClass('FiducialMark') and not InRegion(1000,500,4000,800) and not InPoly] p3: gap=20 ignorepadtopadclearanceinfootprint=FALSE except(13: SMDPad-OutlineEdge)
Clearance Room [WithinRoom('RoomDefinition_1')] p1: gap=4 ignorepadtopadclearanceinfootprint=TRUE except(5: SMDPad-Poly)
Clearance Clearance_Keepouts [((IsTrack Or IsArc) And Not InPoly) And IsFree and IsKeepOut vs ((IsTrack Or IsArc) And Not InPoly) And IsFree and IsKeepOut] p2: gap=0 ignorepadtopadclearanceinfootprint=FALSE
Clearance Clearance_Poly [InPolygon] p3: gap=8 ignorepadtopadclearanceinfootprint=TRUE except(10: Poly-Poly; 15: THPad-Poly)
Clearance Clearance_FiducialMark [IsKeepOut and InComponentClass('FiducialMark') vs IsPad and InComponentClass('FiducialMark')] p4: gap=0 ignorepadtopadclearanceinfootprint=FALSE
Clearance [All] p5: gap=7.87 ignorepadtopadclearanceinfootprint=TRUE except(3.6: Via-Region; 4.2: Arc-SMDPad Arc-Fill Arc-Region Track-SMDPad SMDPad-SMDPad SMDPad-Fill SMDPad-Region Via-Fill Fill-Poly; 4.5: Arc-Arc Arc-Track Arc-Via Arc-Poly Track-Track Track-Via Track-Fill Track-Poly Track-Region SMDPad-Poly; 5: Arc-THPad Track-THPad SMDPad-THPad THPad-THPad Via-Via Via-Poly; 6: SMDPad-Via Fill-Fill Fill-Region Poly-Poly Poly-Region Region-Region; 7.6: THPad-Region)
ComponentClearance ComponentClearance_MountingHoles_FiducialMarks [InComponentClass('Mounting Holes') vs InComponentClass('FiducialMark')] p1: gap=50 collisioncheckmode=3 verticalgap=10 showdistances=FALSE
ComponentClearance ComponentClearance_Shunt [InComponentClass('Header') vs InComponentClass('Shunt')] p2: gap=0 collisioncheckmode=3 verticalgap=0 showdistances=FALSE
ComponentClearance ComponentClearance_Logo [InComponentClass('Logo')] p3: gap=50 collisioncheckmode=3 verticalgap=10 showdistances=FALSE
ComponentClearance ComponentClearance_ScrewToNut [(HasFootprint('NY PMS 440 0025 PH')) vs (HasFootprint('Keystone_1902C'))] p4: gap=5 collisioncheckmode=3 verticalgap=10 showdistances=FALSE
ComponentClearance ComponentClearance_MountingHoles [InComponentClass('Mounting Holes')] p5: gap=20 collisioncheckmode=3 verticalgap=100000 showdistances=FALSE
ComponentClearance ComponentClearance_SmallPassives [HasFootprint('0201*') or HasFootprint('0402*') or HasFootprint('0508') or HasFootprint('0603*') or HasFootprint('0612') or HasFootprint('0805*') or HasFootprint('0815*') or HasFootprint('0830*') or HasFootprint('1206*') or HasFootprint('1210*') or HasFootprint('1808*') or HasFootprint('1812*') or HasFootprint('1825*') or HasFootprint('2010*') or HasFootprint('2220*') or HasFootprint('2225*') or HasFootprint('2512*') or HasFootprint('2728*') or HasFootprint('3518*') vs HasFootprint('0201*') or HasFootprint('0402*') or HasFootprint('0508') or HasFootprint('0603*') or HasFootprint('0612') or HasFootprint('0805*') or HasFootprint('0815*') or HasFootprint('0830*') or HasFootprint('1206*') or HasFootprint('1210*') or HasFootprint('1808*') or HasFootprint('1812*') or HasFootprint('1825*') or HasFootprint('2010*') or HasFootprint('2220*') or HasFootprint('2225*') or HasFootprint('2512*') or HasFootprint('2728*') or HasFootprint('3518*')] p6: gap=10 collisioncheckmode=3 verticalgap=10 showdistances=FALSE
ComponentClearance ComponentClearance_THtoSMT [IsThruComponent vs IsSMTComponent] p7: gap=10 collisioncheckmode=3 verticalgap=10 showdistances=FALSE
ComponentClearance ComponentClearance_THtoTH [IsThruComponent vs IsThruComponent] p8: gap=15 collisioncheckmode=3 verticalgap=15 showdistances=FALSE
ComponentClearance [All] p9: gap=10 collisioncheckmode=3 verticalgap=10 showdistances=FALSE
DiffPairsRouting 90E [InDifferentialPairClass('90E')] p1: maxlimit=10 minlimit=6.5 mostfreqgap=10 toplayer_maxgap=6.5 toplayer_prefgap=6.5 toplayer_minwidth=5 toplayer_maxwidth=5 toplayer_prefwidth=5 midlayer1_mingap=8.5 midlayer1_minwidth=5 midlayer1_maxwidth=15 midlayer1_prefwidth=15 midlayer2_mingap=8.5 midlayer2_maxgap=8.5 midlayer2_prefgap=8.5 midlayer2_minwidth=5 midlayer2_maxwidth=5 midlayer2_prefwidth=5 midlayer3_mingap=10 midlayer3_minwidth=15 midlayer3_maxwidth=15 midlayer3_prefwidth=15 midlayer4_mingap=10 midlayer4_minwidth=15 midlayer4_maxwidth=15 midlayer4_prefwidth=15 midlayer5_mingap=10 midlayer5_minwidth=15 midlayer5_maxwidth=15 midlayer5_prefwidth=15 midlayer6_mingap=10 midlayer6_minwidth=15 midlayer6_maxwidth=15 midlayer6_prefwidth=15 midlayer7_mingap=8.5 midlayer7_maxgap=8.5 midlayer7_prefgap=8.5 midlayer7_minwidth=5 midlayer7_maxwidth=5 midlayer7_prefwidth=5 midlayer8_mingap=10 midlayer8_minwidth=15 midlayer8_maxwidth=15 midlayer8_prefwidth=15 bottomlayer_prefgap=6.5 bottomlayer_minwidth=5 bottomlayer_maxwidth=5 bottomlayer_prefwidth=5 maxuncoupledlength=500
DiffPairsRouting 100E [InDifferentialPairClass('100E')] p2: maxlimit=100 minlimit=7.5 mostfreqgap=10 toplayer_maxgap=7.5 toplayer_prefgap=7.5 toplayer_minwidth=4 toplayer_maxwidth=4 toplayer_prefwidth=4 midlayer1_mingap=10 midlayer1_minwidth=15 midlayer1_maxwidth=15 midlayer1_prefwidth=15 midlayer2_mingap=9 midlayer2_maxgap=9 midlayer2_prefgap=9 midlayer2_minwidth=4 midlayer2_maxwidth=4 midlayer2_prefwidth=4 midlayer3_mingap=10 midlayer3_minwidth=15 midlayer3_maxwidth=15 midlayer3_prefwidth=15 midlayer4_mingap=10 midlayer4_minwidth=15 midlayer4_maxwidth=15 midlayer4_prefwidth=15 midlayer5_mingap=10 midlayer5_minwidth=15 midlayer5_maxwidth=15 midlayer5_prefwidth=15 midlayer6_mingap=10 midlayer6_minwidth=15 midlayer6_maxwidth=15 midlayer6_prefwidth=15 midlayer7_mingap=9 midlayer7_maxgap=9 midlayer7_prefgap=9 midlayer7_minwidth=4 midlayer7_maxwidth=4 midlayer7_prefwidth=4 midlayer8_mingap=10 midlayer8_minwidth=15 midlayer8_maxwidth=15 midlayer8_prefwidth=15 bottomlayer_maxgap=7.5 bottomlayer_prefgap=7.5 bottomlayer_minwidth=4 bottomlayer_maxwidth=4 bottomlayer_prefwidth=4 maxuncoupledlength=1000
FabricationTestPointUsage TestPointUsage [All] p1: valid=2 allowmultiple=FALSE
FabricationTestpoint Testpoint [All] p1: side=3 testpointundercomponent=TRUE minsize=40 maxsize=100 preferedsize=60 minholesize=0 maxholesize=40 preferedholesize=32 testpointgrid=1 allowsidetop=TRUE allowsidebottom=TRUE usegrid=TRUE gridtolerance=0.01
FanoutControl Fanout_LCC [IsLCC] p1: bgadir=Out bgaviamode=Centered fanoutstyle=Auto fanoutdirection=Alternating viagrid=1 // Fanout_LCC (Default Rule)
FanoutControl Fanout_BGA [IsBGA] p2: bgadir=Out bgaviamode=Centered fanoutstyle=Auto fanoutdirection=Alternating viagrid=1 // Fanout_BGA (Default Rule)
FanoutControl Fanout_Default [All] p4: bgadir=Out bgaviamode=Centered fanoutstyle=Auto fanoutdirection=Alternating viagrid=1 // Fanout_Default (Default Rule)
FanoutControl Fanout_Small [(CompPinCount < 5)] p5: bgadir=Out bgaviamode=Centered fanoutstyle=Auto fanoutdirection=OutThenIn viagrid=1 // Fanout_Small (Default Rule)
HoleSize [All] p1: absolutevalues=TRUE maxlimit=251 minlimit=6 maxpercent=80.000 minpercent=20.000
Length SFC [InNetClass('SFC')] p1: maxlimit=1742 minlimit=1732
Length Length_1 [InNetClass('SPI')] p2: maxlimit=3473 minlimit=3463
Length [InNetClass('SD_CARD')] p3: maxlimit=2907 minlimit=2897
MinimumAnnularRing MinimumAnnularRing_ThermalPadVias [IsVia and InAnyComponent] p1: minimumring=5.91
MinimumAnnularRing [All] p2: minimumring=3
MinimumSolderMaskSliver MinimumSolderMaskSliver_Logo [InComponentClass('Logo') vs InComponentClass('Logo')] p1: minsoldermaskwidth=0.7
MinimumSolderMaskSliver [All] p2: minsoldermaskwidth=2
PlaneConnect [All] p1: planeconnectstyle=Direct reliefexpansion=10 reliefentries=4 reliefconductorwidth=10 reliefairgap=10
PolygonConnect [All] p1: connectstyle=Direct reliefconductorwidth=10 reliefentries=4 polygonreliefangle="90 Angle" airgapwidth=10
RoomDefinition RoomDefinition_1 [False vs False] p1: confinementstyle=ConfineIn formatcopy=TRUE lockcomponents=FALSE outline 1303.33,2590.44 1691,2590.44 1691,2196.74 1303.33,2196.74
RoutingVias ThermalPadVias [IsVia and InAnyComponent] p1: holewidth=6 width=19.68 viastyle="Through Hole" minholewidth=6 minwidth=14 maxholewidth=12.99 maxwidth=23.62
RoutingVias [All] p2: holewidth=6 width=34 viastyle="Through Hole" minholewidth=6 minwidth=12 maxholewidth=40 maxwidth=65
SilkToBoardRegionClearance [Not ((IsComment or IsDesignator) And (Hide <> 'False')) and not InRegion(1000,500,4000,800)] p1:
SilkToSilkClearance SilkToSilkClearance_Pb-FreeLogo [(HasFootprint('Pb-Free_Overlay_Medium') OR HasFootprint('Pb-Free_Overlay_Small')) vs (HasFootprint('Pb-Free_Overlay_Medium') OR HasFootprint('Pb-Free_Overlay_Small'))] p1: silktosilkclearance=0
SilkToSilkClearance [All] p2: silktosilkclearance=3.94
SilkToSolderMaskClearance SilkToComponentPadClearance [(IsPad or IsFill or IsRegion) and InAnycomponent] p1: minsilkscreentomaskgap=5 clearancetoexposedcopper=TRUE
SilkToSolderMaskClearance "Silk to Solder Mask Opening" [All] p2: minsilkscreentomaskgap=3.94 clearancetoexposedcopper=FALSE
SolderMaskExpansion [All] p1: expansion=1.97
UnRoutedNet [All] p1: checkbadconnections=TRUE
Width Width_1 [WithinRoom('RoomDefinition_1')] p1: maxlimit=10 minlimit=4 preferedwidth=4
Width 50E_SE [InNetClass('50E_SE')] p2: maxlimit=10 minlimit=4.5 preferedwidth=10 toplayer_minwidth=5.5 toplayer_maxwidth=5.5 toplayer_prefwidth=5.5 midlayer1_minwidth=10 midlayer2_maxwidth=4.5 midlayer2_prefwidth=4.5 midlayer3_minwidth=10 midlayer4_minwidth=10 midlayer5_minwidth=10 midlayer6_minwidth=10 midlayer7_maxwidth=4.5 midlayer7_prefwidth=4.5 midlayer8_minwidth=10 bottomlayer_minwidth=5.5 bottomlayer_maxwidth=5.5 bottomlayer_prefwidth=5.5 minimp=50.000000 maximp=50.000000 favimp=50.000000
Width OV_SPI [InNetClass('OV_SPI')] p3: maxlimit=10 minlimit=4.5 preferedwidth=10 toplayer_minwidth=5.5 toplayer_maxwidth=5.5 toplayer_prefwidth=5.5 midlayer1_minwidth=10 midlayer2_maxwidth=4.5 midlayer2_prefwidth=4.5 midlayer3_minwidth=10 midlayer4_minwidth=10 midlayer5_minwidth=10 midlayer6_minwidth=10 midlayer7_maxwidth=4.5 midlayer7_prefwidth=4.5 midlayer8_minwidth=10 bottomlayer_minwidth=5.5 bottomlayer_maxwidth=5.5 bottomlayer_prefwidth=5.5 minimp=50.000000 maximp=50.000000 favimp=50.000000
Width [All] p4: maxlimit=100 minlimit=4 preferedwidth=10 midlayer3_minwidth=6 midlayer4_minwidth=6 midlayer5_minwidth=6 midlayer6_minwidth=6 midlayer8_minwidth=6 minimp=50.000000 maximp=50.000000 favimp=50.000000 checkconnectedcopper=TRUE
14 further rules are at their usual default settings.

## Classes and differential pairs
net class JTAG: P16_JTAG_TDI P17_JTAG_TDO P19_JTAG_TCK P20_JTAG_TMS
net class SN_SIO: SN_SIO_C SN_SIO_D
net class SFC: SFC_CLK SFC_MOSI0 SFC_MOSI1 SFC_MOSI2 SFC_MOSI3 SFC_SSN
net class OPT: OPT_SCL OPT_SDA
net class SPI: RDY SPI_CLK SPI_CS SPI_MISO SPI_MOSI SYNC
net class SD_CARD: SC_CD SC_CLK SC_CMD SC_D0 SC_D1 SC_D2 SC_D3
net class 50E_SE: AU_AOL AU_AOM AU_MBIAS AU_MIC_IN AU_SHDN OV_RST# OV_RXD1 OV_TXD1 P16_JTAG_TDI P17_JTAG_TDO P19_JTAG_TCK P20_JTAG_TMS SC_CD SC_CLK SC_CMD SC_D0 SC_D1 SC_D2 SC_D3 SI0 SI1 SI2 SN_CCLK SN_PWDN SN_RST# SN_SID SN_SIO_C SN_SIO_D SPI_CLK SPI_CS SPI_MISO SPI_MOSI UART_RX UART_TX
differential pair class 100E: IR MRXC0 MRXD0 MRXD1 SN_IR SNIR SP UART
differential pair class 90E: USB
component class P04_Peripherals: 3.3V_PA 3.3V_SC AOL C1 C2 C8 C9 C10 C11 C12 C15 C17 C43 C45 C46 C49 C55 C56 C57 C58 C59 C60 C62 C66 C113 C115 C118 C123 C124 C131 C132 C134 CN1 CN2 CN3 CN8 D8 FB FB2 FB11 FB12 FREQ IN_PS IR_EN IR_IN1 IR_IN2 L1 LED_EN LED_OUT MBIAS MIC_IN MK1 OUT_PS R2 R3 R5 R7 R9 R10 R14 R62 R64 R67 R68 R72 R76 R77 R78 R79 R85 R86 R88 R90 R95 R138 R139 R140 R163 R164 R165 R166 R167 R168 R184 REF SHDN TP4 U2 U9 U10 U15 U21 U22 VCC_IR VP
component class P03_CC3235MODA_WIFI_Launchpad: 3.3V_MCU C3 C4 C5 C6 C7 C20 C22 C24 C61 C125 C126 C127 C129 C133 C158 C159 C160 C161 C? D1 D2 D5 D6 FB1 FLASH_CLK FLASH_CS FLASH_MISO FLASH_MOSI ID J5 J7 J8 J9 J11 J13 MEAS MEAS_EN MEAS_MCU PS_VCC Q4 Q5 R1 R6 R8 R11 R12 R16 R17 R22 R25 R26 R27 R28 R29 R30 R31 R32 R33 R34 R35 R36 R37 R38 R39 R40 R43 R44 R47 R48 R49 R50 R51 R54 R58 R59 R60 R65 R66 R69 R70 R71 R73 R74 R75 R84 R89 R121 R133 R136 R151 R153 R154 R155 R156 R157 R158 R159 R160 R162 R169 R171 R172 R173 R174 R175 R176 R177 R178 R180 R185 R186 R187 SW1 SW2 TP9 TP13 U1 U6 U18 U19 U20 U24 VCC_ALS VCC_AMP
component class P02_OA7000_Image_Sensor: AOM AVDD C C28 C29 C30 C31 C33 C34 C35 C36 C37 C38 C39 C40 C41 C42 C44 C47 C48 C50 C51 C52 C53 C54 C74 C75 C76 C77 C78 C79 C80 C81 C82 C83 C84 C85 C86 C88 C90 C91 C92 C94 C96 C97 C98 C99 C100 C101 C102 C105 C106 C107 C108 C109 C128 CLK CN4 CN6 CN7 CN9 D D3 D4 DBG0 DBG1 DI DO DVDD FB3 FB4 FB5 FB6 FB7 FB8 FB9 FB10 LR MCLK OV_1.1V OV_1.8V OV_1.35V OV_3.3V Q2 Q3 R15 R18 R19 R20 R21 R23 R24 R45 R46 R52 R53 R55 R56 R57 R61 R63 R80 R81 R82 R83 R96 R97 R98 R104 R106 R111 R113 R115 R117 R119 R120 R122 R125 R126 R130 R132 R143 R144 R161 R179 R181 R182 R183 RST SID SW3 U17 VCC_MEM VDDAO VeFuse VMID VREF VREF_AU Y1
component class P01_Power_Delivery: 1.1V 1.8V 1.35V 2.5V 3.3V BAT C13 C14 C16 C18 C19 C21 C23 C25 C26 C27 C63 C64 C65 C67 C68 C69 C70 C71 C72 C73 C87 C89 C93 C95 C103 C104 C110 C111 C112 C114 C116 C117 C119 C120 C121 C122 C130 C138 C146 C147 C155 C156 C157 CN5 EN EN_1.35V IN1 IN2 IN_1.1V IN_1.8V IN_1.35V IN_2.5V IN_3.3V J1 J2 J4 J6 J10 J12 J14 J23 J24 L2 L3 L4 L5 L6 ON PG_1.1V PG_1.8V PG_1.35V PG_3.3V PWR_EN Q1 R4 R13 R41 R42 R87 R91 R92 R93 R94 R99 R100 R101 R102 R103 R105 R107 R108 R109 R110 R112 R114 R116 R118 R123 R124 R127 R128 R129 R131 R134 R135 R137 R141 R142 R145 R146 R147 R148 R149 R150 R152 R170 SYSON1 SYSON2 TP35 TP39 TP43 TP81 U3 U4 U5 U7 U8 U11 U12 U13 U14 U16 USB VBAT VOUT1 VOUT2
component class Header: CN8 CN9 J2 J4 J6 J9 J10 J11 J12 J13 J14
component class Label: LBL1
component class AssemblyNote: ZZ1 ZZ2 ZZ3 ZZ4
component class FiducialMark: FID1 FID2 FID3 FID6
component class Encoder_Main_Board_Hardware: FID1 FID2 FID3 FID6 H1 H2 H3 H4 H5 H6 H7 H8 H9 H10 H11 H12 LBL1 Logo1 Logo2 Logo3 Logo4 ZZ1 ZZ2 ZZ3 ZZ4
component class Logo: Logo3
component class "Mounting Holes": H1 H2 H3 H4 H5 H6
differential pair UART: +UART_RX -UART_TX
differential pair SN_IR: +SN_IR_IN1 -SN_IR_IN2
differential pair MRXD0: +MRXDN0 -MRXDP0
differential pair MRXD1: +MRXDN1 -MRXDP1
differential pair MRXC0: +MRXCN0 -MRXCP0
differential pair SP: +SPKP -SPKN
differential pair IR: +IR-CUT_P -IR-CUT_N
differential pair USB: +USB_DP -USB_DN

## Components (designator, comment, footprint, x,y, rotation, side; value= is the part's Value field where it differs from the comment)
1.1V "TP_SM_1MM" TP_SM_1MM 778.5,2288 r180 top
1.8V "TP_SM_1MM" TP_SM_1MM 914.89,2689.02 r180 top
1.35V "TP_SM_1MM" TP_SM_1MM 2172.62,2294 r270 top
2.5V "TP_SM_1MM" TP_SM_1MM 1234.22,2093.36 r90 top
3.3V "TP_SM_1MM" TP_SM_1MM 872,2611 r180 top
3.3V_MCU "TP_SM_1MM" TP_SM_1MM 313,474 r180 top
3.3V_PA "RCU-0C" TE_RCU 737.57,1733.76 r0 top
3.3V_SC "TP_SM_1MM" TP_SM_1MM 146.92,2616 r90 top
AOL "TP_SM_1MM" TP_SM_1MM 496.71,1757.43 r180 top
AOM "TP_SM_1MM" TP_SM_1MM 1251.07,2575 r90 top
AVDD "TP_SM_1MM" TP_SM_1MM 1290.89,3345 r270 top
BAT "TP_SM_1MM" TP_SM_1MM 538,3547.54 r0 top
C "TP_SM_1MM" TP_SM_1MM 1196,2450 r90 top
C1 "GRM155R71C102KA01D" 0402#1 319,2035.83 r0 top value=1000pF
C2 "GRM155R71C102KA01D" 0402#1 321.31,1856.07 r0 top value=1000pF
C3 "GRM155R71C104KA88D" 0402#2 336.31,622.67 r0 top value=0.1uF
C4 "GRM155R71C104KA88D" 0402#2 336.31,589 r180 top value=0.1uF
C5 "GRM155R71C104KA88D" 0402#2 336.31,555.33 r180 top value=0.1uF
C6 "GRM155R71C104KA88D" 0402#2 336.31,521.67 r180 top value=0.1uF
C7 "C1210C107M4PAC7800" 1210_270 424.85,412.93 r270 top value=100uF
C8 "GRM155R71C104KA88D" 0402#2 421,2030 r180 top value=0.1uF
C9 "GRM188Z71C475KE21D" 0603 532.71,1944.34 r0 top value=4.7uF
C10 "GRM155R71C333KA01D" 0402#1 520.94,1831.47 r180 top value=0.033uF
C11 "GRM155R71C333KA01D" 0402#1 522.38,2076.76 r180 top value=0.033uF
C12 "GRM155R71C104KA88D" 0402#2 520,1990 r180 top value=0.1uF
C13 "GCM188R71C105MA64D" 0603 604.02,3448.43 r0 top value=1uF
C14 "GCM188R71C105MA64D" 0603 608,3708 r0 top value=1uF
C15 "GCM188R71C105MA64D" 0603 576.34,2213.79 r270 top value=1uF
C16 "885012205037" 0402#1 603.24,3503.29 r0 top value=0.1uF
C17 "GRM188Z71C225KE43" 0603 625.96,2338.79 r270 top value=2.2uF
C18 "GCM188R71C105MA64D" 0603 654,2584.79 r270 top value=1uF
C19 "GRM155R71C104KA88D" 0402#2 737.57,2496.79 r180 top value=0.1uF
C20 "GRM155R71C104KA88D" 0402#2 799.69,342 r180 top value=0.1uF
C21 "GCM188R71C105MA64D" 0603 822.37,3644.51 r90 top value=1uF
C22 "GRM155R71C104KA88D" 0402#2 879.69,314 r0 top value=0.1uF
C23 "885012205037" 0402#1 1026.7,3654.65 r90 top value=0.1uF
C24 "GCM188R71C105MA64D" 0603 1097.86,599.44 r180 top value=1uF
C25 "GCM188R71C105MA64D" 0603 1083.7,3656.65 r90 top value=1uF
C26 "GCM188R71C105MA64D" 0603 1150,2094 r180 top value=1uF
C27 "GCM188R71C105MA64D" 0603 1154.07,1950.85 r180 top value=1uF
C28 "C1005C0G1H330J050BA" 0402#1 1216,3008 r0 top value=33pF
C29 "GRM155R71C104KA88D" 0402#2 1208.48,2964.71 r0 top value=0.1uF
C30 "GRM155R71C104KA88D" 0402#2 1189,3162 r270 top value=0.1uF
C31 "CL21B106KOQNNNE" 0805_HV 1251,2639 r0 top value=10uF
C33 "GCM188R71C105MA64D" 0603 1220.46,2360.19 r270 top value=1uF
C34 "GRM188Z71C475KE21D" 0603 1288.69,3192.03 r0 top value=4.7uF
C35 "GRM188Z71C225KE43" 0603 1328.61,2134.7 r180 top value=2.2uF
C36 "GRM188Z71C225KE43" 0603 1328.61,2075.16 r180 top value=2.2uF
C37 "GRM188Z71C475KE21D" 0603 1305.48,3010.88 r90 top value=4.7uF
C38 "GRM188Z71C475KE21D" 0603 1416.2,2654.88 r0 top value=4.7uF
C39 "GRM033Z71C104KE14D" 0201 1409.55,2610.4 r180 top value=0.1uF
C40 "GRM155R71C104KA88D" 0402#2 1411,3068 r90 top value=0.1uF
C41 "GRM155R71C104KA88D" 0402#2 1445.27,3107.55 r270 top value=0.1uF
C42 "GRM188Z71C225KE43" 0603 1502,2117.73 r270 top value=2.2uF
C43 "CL21B106KOQNNNE" 0805_HV 1552,3457 r270 top value=10uF
C44 "GRM188Z71C225KE43" 0603 1606.08,2107.44 r270 top value=2.2uF
C45 "CL21B106KOQNNNE" 0805_HV 1638,3457 r270 top value=10uF
C46 "CL21B106KOQNNNE" 0805_HV 1723,3457 r270 top value=10uF
C47 "GRM033Z71C104KE14D" 0201 1738.83,2263.64 r180 top value=0.1uF
C48 "GRM033Z71C104KE14D" 0201 1752.5,2331 r180 top value=0.1uF
C49 "GCM188R71C105MA64D" 0603 1796,3456 r90 top value=1uF
C50 "GRM033Z71C104KE14D" 0201 1820,2229.35 r90 top value=0.1uF
C51 "GRM033Z71C104KE14D" 0201 1853.25,2291.5 r0 top value=0.1uF
C52 "GCM188R71C105MA64D" 0603 1874,2204.17 r270 top value=1uF
C53 "GRM1555C1H8R2BA01D" FP-GRM1555C1H8R2BA01D_0402-MFG 1870.19,2460.32 r180 top value=8.2pF
C54 "GRM1555C1H8R2BA01D" FP-GRM1555C1H8R2BA01D_0402-MFG 1870.23,2402.01 r180 top value=8.2pF
C55 "GRM1555C1H100FA01D" 0402#1 1944,3294 r0 top value=10pF
C56 "GCM188R71C105MA64D" 0603 2137,3315 r180 top value=1uF
C57 "CGA6P1X7R1C226M250AC" 1210_280 2240,3690.81 r0 top value=22uF
C58 "CL21B106KOQNNNE" 0805_HV 2239,3589.17 r0 top value=10uF
C59 "GCM188R71C105MA64D" 0603 2234,3428 r180 top value=1uF
C60 "GCM188R71C105MA64D" 0603 2208.65,3174.49 r90 top value=1uF
C61 "GCM188R71C105MA64D" 0603 2198,1972 r0 bottom value=1uF
C62 "GCM188R71C105MA64D" 0603 2206.42,3663.17 r270 bottom value=1uF
C63 "C1608X7S1A475K080AC" 0603 2164,2180 r90 bottom value=4.7uF
C64 "GRM21BR61E106KA73L" 0805_HV 2145,2353 r90 bottom value=10uF
C65 "GRM21BR61A476ME15L" 0805_HV 2059,2352 r90 bottom value=47uF
C66 "GCM188R71C105MA64D" 0603 1989.41,3652.41 r270 bottom value=1uF
C67 "GRM21BR61A476ME15L" 0805_HV 1940.88,1282.21 r90 bottom value=47uF
C68 "GRM21BR61A476ME15L" 0805_HV 1940,1007 r90 bottom value=47uF
C69 "GRM1555C1H121JA01D" 0402#1 1928,2184.14 r270 bottom value=120pF
C70 "CL10A226MO7JZNC" 0603 1857.37,907.34 r90 bottom value=22uF
C71 "GRM155R71C104KA88D" 0402#2 1832.34,2029 r0 bottom value=0.1uF
C72 "CL21B106KOQNNNE" 0805_HV 1781.79,907.87 r90 bottom value=10uF
C73 "C1608X5R1A226M080AC" 0603 1786.96,1283.21 r90 bottom value=22uF
C74 "GRM033Z71C104KE14D" 0201 1759.01,2299 r180 bottom value=0.1uF
C75 "GRM033Z71C104KE14D" 0201 1752.5,2331 r180 bottom value=0.1uF
C76 "GRM033Z71C104KE14D" 0201 1702,2530 r270 bottom value=0.1uF
C77 "GRM033Z71C104KE14D" 0201 1675,2468.99 r270 bottom value=0.1uF
C78 "GRM033Z71C104KE14D" 0201 1655,2324 r180 bottom value=0.1uF
C79 "GRM033Z71C104KE14D" 0201 1664,2370 r270 bottom value=0.1uF
C80 "GRM033Z71C104KE14D" 0201 1645,2258 r180 bottom value=0.1uF
C81 "GRM033Z71C104KE14D" 0201 1644,2414 r180 bottom value=0.1uF
C82 "GRM033Z71C104KE14D" 0201 1625,2447 r0 bottom value=0.1uF
C83 "GRM033Z71C104KE14D" 0201 1609,2369 r270 bottom value=0.1uF
C84 "GRM033Z71C104KE14D" 0201 1582,2237 r180 bottom value=0.1uF
C85 "GRM033Z71C104KE14D" 0201 1556,2405 r0 bottom value=0.1uF
C86 "GRM033Z71C104KE14D" 0201 1539,2303 r180 bottom value=0.1uF
C87 "CC0402MRX5R7BB475" 0402_065 1542,906.38 r90 bottom value=4.7uF
C88 "GRM033Z71C104KE14D" 0201 1532,2358 r180 bottom value=0.1uF
C89 "CC0402MRX5R7BB475" 0402_065 1524.17,1280.21 r90 bottom value=4.7uF
C90 "GRM033Z71C104KE14D" 0201 1513.15,2537.5 r270 bottom value=0.1uF
C91 "GRM033Z71C104KE14D" 0201 1513,2476 r270 bottom value=0.1uF
C92 "GRM033Z71C104KE14D" 0201 1513,2406.01 r90 bottom value=0.1uF
C93 "GRM188R60J106ME47D" 0603 1488,903 r90 bottom value=10uF
C94 "GRM033Z71C104KE14D" 0201 1475,2360 r180 bottom value=0.1uF
C95 "GRM188R60J226MEA0D" 0603 1470.17,1277.21 r90 bottom value=22uF
C96 "GRM033Z71C104KE14D" 0201 1482,2270.15 r90 bottom value=0.1uF
C97 "GRM033Z71C104KE14D" 0201 1469,2406 r0 bottom value=0.1uF
C98 "GRM033Z71C104KE14D" 0201 1446,2327 r0 bottom value=0.1uF
C99 "GRM033Z71C104KE14D" 0201 1434,2296 r0 bottom value=0.1uF
C100 "GRM033Z71C104KE14D" 0201 1417,2359 r180 bottom value=0.1uF
C101 "GRM033Z71C104KE14D" 0201 1403.06,2462 r0 bottom value=0.1uF
C102 "GCM188R71C105MA64D" 0603 1390.52,2118.56 r270 bottom value=1uF
C103 "GRM155R71C104KA88D" 0402#2 1392.79,1025.7 r270 bottom value=0.1uF
C104 "GRM155R70J105MA12D" 0402#1 1383,1145.59 r270 bottom value=1uF
C105 "GRM033Z71C104KE14D" 0201 1360,2559.36 r180 bottom value=0.1uF
C106 "GRM033Z71C104KE14D" 0201 1354.73,2298.62 r0 bottom value=0.1uF
C107 "GRM033Z71C104KE14D" 0201 1365,2415 r90 bottom value=0.1uF
C108 "GRM033Z71C104KE14D" 0201 1350,2505.82 r180 bottom value=0.1uF
C109 "GRM188Z71C475KE21D" 0603 1232,2471 r180 bottom value=4.7uF
C110 "C1608X7S1A475K080AC" 0603 1018.98,2289 r180 bottom value=4.7uF
C111 "GRM21BR61A476ME15L" 0805_HV 968,2931 r0 bottom value=47uF
C112 "GRM188R60G106ME47D" 0603 955,2859 r0 bottom value=10uF
C113 "CL21B106KOQNNNE" 0805_HV 912.45,3832.72 r180 bottom value=10uF
C114 "GRM1555C1H121JA01D" 0402#1 933,2094 r0 bottom value=120pF
C115 "" 0402#2 933,3891 r0 bottom value=0.1uF
C116 "GRM155R60G106ME44D" 0402_070 924,2257 r270 bottom value=10uF
C117 "GCM188R71C105MA64D" 0603 884.12,2568.58 r270 bottom value=1uF
C118 "" 0402#2 859.66,3887.87 r180 bottom value=0.1uF
C119 "CGA6P1X7R1C226M250AC" 1210_280 823,3650.76 r90 bottom value=22uF
C120 "GRM21BR61A476ME15L" 0805_HV 830.79,2219.37 r270 bottom value=47uF
C121 "C1608X7S1A475K080AC" 0603 790.99,2846.57 r0 bottom value=4.7uF
C122 "GRM1555C1H121JA01D" 0402#1 789,3065 r180 bottom value=120pF
C123 "" 0402#2 811,3924 r90 bottom value=0.1uF
C124 "" 0402#2 811,4003.68 r90 bottom value=0.1uF
C125 "GRM1555C1H102JA01D" 0402#1 658.25,3296.41 r270 bottom value=1000pF
C126 "GRM155R71C104KA88D" 0402#2 598.25,3285.41 r180 bottom value=0.1uF
C127 "C1210C107M4PAC7800" 1210_270 426,412 r270 bottom value=100uF
C128 "GCM188R71C105MA64D" 0603 384.52,2749 r270 bottom value=1uF
C129 "GCM188R71C105MA64D" 0603 353,3721 r90 bottom value=1uF
C130 "GRM155R71C104KA88D" 0402#2 322,3487.31 r270 bottom value=0.1uF
C131 "GRM155R71C104KA88D" 0402#2 124.44,3015 r270 bottom value=0.1uF
C132 "885012005055" 0402#1 88.52,3073.44 r180 bottom value=10pF
C133 "CL21B106KOQNNNE" 0805_HV 88.06,3724.17 r270 bottom value=10uF
C134 "GRM155R71C104KA88D" 0402#2 85,3015 r270 bottom value=0.1uF
CLK "TP_SM_1MM" TP_SM_1MM 1512,2626.58 r90 top
CN1 "282834-2" TEC_282834-2 127,1950 r90 top
CN2 "693071010811" FP-693071010811_CONN_SMT_MEMORY-MFG 324.57,2953.81 r270 top locked
CN3 "53398-0271" 0533980271 706.58,3911 r0 top
CN4 "FX12B-40P-0.4SV" Hirose_FX12B-40P-0_4SV 1041,3072.13 r0 top
CN5 "ZX62R-B-5P(30)" Hirose_ZX62R-B-5P 1374.5,4086.89 r90 top
CN6 "OA7000" FP-OA7000_BGA169-IPC_C 1500.18,2393.59 r180 top locked
CN7 "FX12B-40P-0.4SV" Hirose_FX12B-40P-0_4SV 1580.24,3072.13 r0 top
CN8 "PEC01DAAN" Sullins_PxC01DAAN 1581.88,3779.51 r180 top
CN9 "GRPB041VWVN-RC" Sullins_GRPB041VWVN-RC 2290,3031 r270 bottom
D "TP_SM_1MM" TP_SM_1MM 1249.79,2494.03 r90 top
D1 "150060BS75000" WL-SMCW_Blue 44,1742.5 r90 top value=Blue
D2 "150060RS75000" WL-SMCW_RED 45,1585 r270 top value=Red
D3 "150060YS75000" WL-SMCW_YELLOW 65.36,2412.39 r90 top value=Yellow
D4 "150060GS75000" WL-SMCW_GREEN 69.33,2551.08 r270 top value=Green
D5 "ESD321DPYR" DPY0002A 795.62,284 r0 top
D6 "ESD321DPYR" DPY0002A 876.2,255 r180 top
D8 "FSV240AF" SMA 1889,3570 r270 top value=40V
DBG0 "TP_SM_1MM" TP_SM_1MM 1733,2061.48 r90 top
DBG1 "TP_SM_1MM" TP_SM_1MM 1796.52,2115.65 r90 top
DI "TP_SM_1MM" TP_SM_1MM 1846.54,2521.7 r90 top
DO "TP_SM_1MM" TP_SM_1MM 1561.87,2685.57 r90 top
DVDD "TP_SM_1MM" TP_SM_1MM 807.88,3327.59 r90 top
EN "TP_SM_1MM" TP_SM_1MM 1042.21,1995.96 r90 top
EN_1.35V "TP_SM_1MM" TP_SM_1MM 2000,2101.84 r180 top
FB "TP_SM_1MM" TP_SM_1MM 1973,3157 r90 top
FB1 "BLM18KG121TN1D" FP-BLM18KG121TN1D_0603-MFG 226.8,522.18 r0 top
FB2 "BLM18KG121TN1D" FP-BLM18KG121TN1D_0603-MFG 611.6,1798.57 r90 top
FB3 "BLM18KG121TN1D" FP-BLM18KG121TN1D_0603-MFG 1283.77,3130.18 r180 top
FB4 "BLM18KG121TN1D" FP-BLM18KG121TN1D_0603-MFG 1368.24,3012.75 r270 top
FB5 "BLM18KG121TN1D" FP-BLM18KG121TN1D_0603-MFG 1672,2106.08 r90 top
FB6 "BLM18KG121TN1D" FP-BLM18KG121TN1D_0603-MFG 1778.52,2544.85 r270 bottom
FB7 "BLM18KG121TN1D" FP-BLM18KG121TN1D_0603-MFG 1256.43,2007.82 r0 bottom
FB8 "BLM18KG121TN1D" FP-BLM18KG121TN1D_0603-MFG 1232.28,2526 r0 bottom
FB9 "BLM18KG121TN1D" FP-BLM18KG121TN1D_0603-MFG 1231,2604.55 r0 bottom
FB10 "BLM18KG121TN1D" FP-BLM18KG121TN1D_0603-MFG 1220.39,2257.7 r0 bottom
FB11 "BLM18KG121TN1D" FP-BLM18KG121TN1D_0603-MFG 1024,3803 r90 bottom
FB12 "BLM18KG121TN1D" FP-BLM18KG121TN1D_0603-MFG 85.52,2947.59 r0 bottom
FID1 "Fiducial" Fiducial10-20 422,4099.98 r90 top
FID2 "Fiducial" Fiducial10-20 1928,4098 r90 top
FID3 "Fiducial" Fiducial10-20 2249.03,692 r90 top
FID6 "Fiducial" Fiducial10-20 422,4099.98 r90 bottom
FID6_1 "Fiducial" Fiducial10-20 1929.01,4103.61 r90 bottom
FID6_2 "Fiducial" Fiducial10-20 2249.03,692 r90 bottom
FLASH_CLK "TP_SM_1MM" TP_SM_1MM 1075.53,1362 r180 top
FLASH_CS "TP_SM_1MM" TP_SM_1MM 1075.53,1288 r180 top
FLASH_MISO "TP_SM_1MM" TP_SM_1MM 1076.28,1223.6 r180 top
FLASH_MOSI "TP_SM_1MM" TP_SM_1MM 1076.28,1433 r180 top
FREQ "TP_SM_1MM" TP_SM_1MM 2004.08,3765 r180 top
H1 "NY PMS 440 0025 PH" "NY PMS 440 0025 PH" 188,323 r0 top
H2 "NY PMS 440 0025 PH" "NY PMS 440 0025 PH" 191.12,3978.99 r0 top
H3 "NY PMS 440 0025 PH" "NY PMS 440 0025 PH" 387,2473 r0 top
H4 "NY PMS 440 0025 PH" "NY PMS 440 0025 PH" 2107,2761 r0 top
H5 "NY PMS 440 0025 PH" "NY PMS 440 0025 PH" 2167.32,473 r0 top
H6 "NY PMS 440 0025 PH" "NY PMS 440 0025 PH" 2167.32,3979 r0 top
H7 "1902C" Keystone_1902C 2167.32,3979 r180 bottom
H8 "1902C" Keystone_1902C 2167.09,473.01 r180 bottom
H9 "1902C" Keystone_1902C 2107,2761 r180 bottom
H10 "1902C" Keystone_1902C 387,2473 r180 bottom
H11 "1902C" Keystone_1902C 190.89,3979 r180 bottom
H12 "1902C" Keystone_1902C 187.77,323.01 r180 bottom
ID "TP_SM_1MM" TP_SM_1MM 1071.7,394.05 r0 top
IN1 "TP_SM_1MM" TP_SM_1MM 1470.17,1245.72 r270 top
IN2 "TP_SM_1MM" TP_SM_1MM 1381,843.22 r270 top
IN_1.1V "TP_SM_1MM" TP_SM_1MM 1102.32,2336 r90 top
IN_1.8V "TP_SM_1MM" TP_SM_1MM 700,2827 r180 top
IN_1.35V "TP_SM_1MM" TP_SM_1MM 2206,2093 r0 top
IN_2.5V "TP_SM_1MM" TP_SM_1MM 1200.83,1844.07 r180 top
IN_3.3V "TP_SM_1MM" TP_SM_1MM 702.69,2646.83 r180 top
IN_PS "TP_SM_1MM" TP_SM_1MM 2066,3765 r270 top
IR_EN "TP_SM_1MM" TP_SM_1MM 1008,3849 r90 top
IR_IN1 "TP_SM_1MM" TP_SM_1MM 1008,3957.12 r90 top
IR_IN2 "TP_SM_1MM" TP_SM_1MM 976.71,4077 r90 top
J1 "1715721" PhoenixContact_1715721 211.52,3495 r270 top
J2 "M22-2510205" Harwin_M22-2510205 1058.35,2548 r90 bottom
J4 "M22-2510205" Harwin_M22-2510205 1939,739.37 r90 bottom
J5 "FTSH-105-01-F-D-K" Samtec_FTSH-105-01-x-D-K 2202.7,1391.13 r0 bottom
J6 "M22-2510205" Harwin_M22-2510205 2260,2420.75 r270 bottom
J7 "SSQ-110-03-T-D" BoosterPack_40pin_J1J3 1775.78,1834.79 r90 bottom locked
J8 "SSQ-110-03-T-D" BoosterPack_40pin_J2J4 1775.78,134.79 r90 bottom locked
J9 "951204-8622-AR" 3M_951204-8622 2161.28,863 r90 bottom
J10 "M22-2510205" Harwin_M22-2510205 1814,1112 r0 bottom
J11 "61300621121" Wurth_61300621121 1068,1588.27 r270 bottom
J12 "M22-2510205" Harwin_M22-2510205 1021.83,2689.02 r180 bottom
J13 "TSW-105-07-G-D" TSW-105-07-G-D 744,442 r0 bottom
J14 "M22-2510205" Harwin_M22-2510205 724,2402 r0 bottom
L1 "XAL4030-472MEC" FP-XAL4030-472MEC_SMD2-MFG 2058,3581 r180 top
L2 "DFE201610E-R47M=P2" DFE201610E 2245.46,2237.29 r270 bottom value=470nH
L3 "XFL4020-222MEB" XFL4020 1610.87,755.99 r0 bottom value=2.2uH
L4 "DFE201610E-R47M=P2" DFE201610E 1629,1169 r180 bottom value=470nH
L5 "DFE201610E-R47M=P2" DFE201610E 962,2356 r0 bottom value=470nH
L6 "DFE201610E-R47M=P2" DFE201610E 847.99,2759.57 r180 bottom value=470nH
LBL1 "THT-14-423-10" Label_650x200 412.54,1747.11 r270 bottom
LED_EN "TP_SM_1MM" TP_SM_1MM 2252,3321 r180 top
LED_OUT "TP_SM_1MM" TP_SM_1MM 1791.23,3548.31 r0 top
Logo1 "FCC disclaimer" FCC_disclaimer 2636.38,571.2 r90 bottom
Logo2 "WEEE logo" WEEE_Minimum 1098,201 r180 bottom
Logo3 "Texas Instruments" TI_Stacked_Overlay_Small 686.41,1632.11 r90 bottom
Logo4 "CE Mark" CE_Mark_5mm 827.88,139 r180 bottom
LR "TP_SM_1MM" TP_SM_1MM 1507,2686.43 r90 top
MBIAS "TP_SM_1MM" TP_SM_1MM 883,2419.81 r90 top
MCLK "TP_SM_1MM" TP_SM_1MM 1602,2629 r90 top
MEAS "TP_SM_1MM" TP_SM_1MM 536,3272.22 r180 top
MEAS_EN "TP_SM_1MM" TP_SM_1MM 259.15,3762.54 r180 top
MEAS_MCU "TP_SM_1MM" TP_SM_1MM 183.72,2278 r90 top
MIC_IN "TP_SM_1MM" TP_SM_1MM 781.95,2213.1 r180 top
MK1 "CMA-6542TF-K" CUI_CMA-6542TF-K 795,1977 r270 top
ON "TP_SM_1MM" TP_SM_1MM 861.43,2512.38 r180 top
OUT_PS "TP_SM_1MM" TP_SM_1MM 1922.87,3768.45 r0 top
OV_1.1V "TP_SM_1MM" TP_SM_1MM 1058.49,2224.44 r180 top
OV_1.8V "TP_SM_1MM" TP_SM_1MM 1246.25,2208.13 r90 top
OV_1.35V "TP_SM_1MM" TP_SM_1MM 2051,2367.42 r180 top
OV_3.3V "TP_SM_1MM" TP_SM_1MM 1774.34,2671.61 r270 top
PG_1.1V "TP_SM_1MM" TP_SM_1MM 1006.23,2165.13 r0 top
PG_1.8V "TP_SM_1MM" TP_SM_1MM 697.73,2892.32 r90 top
PG_1.35V "TP_SM_1MM" TP_SM_1MM 2207.53,2191.09 r180 top
PG_3.3V "TP_SM_1MM" TP_SM_1MM 1727,1279 r90 top
PS_VCC "TP_SM_1MM" TP_SM_1MM 358.9,3778.47 r180 top
PWR_EN "TP_SM_1MM" TP_SM_1MM 1470.37,1105.91 r0 top
Q1 "SI2323DS" SOT-23 486.7,3373.78 r90 top value=-20V
Q2 "NTS4001NT1G" FP-NTS4001NT1G_SC-70-MFG 109.6,2376.41 r180 bottom
Q3 "NTS4001NT1G" FP-NTS4001NT1G_SC-70-MFG 103.73,2588 r180 bottom
Q4 "NTS4001NT1G" FP-NTS4001NT1G_SC-70-MFG 82.69,1623.71 r180 bottom
Q5 "NTS4001NT1G" FP-NTS4001NT1G_SC-70-MFG 81,1723.3 r180 bottom
R1 "RMCF0603ZT0R00" 0603 226.84,582.95 r180 top value=0
R2 "RMCF0603ZT0R00" 0603 329,1979 r180 top value=0
R3 "RMCF0603ZT0R00" 0603 329,1909 r180 top value=0
R4 "ERJ-2GEJ101X" 0402#1 384.03,3264.18 r0 top value=100
R5 "ERJPA2F1002X" 0402#1 423,2073 r180 top value=10.0k
R6 "ERJ-2RKF1003X" 0402#1 434.39,574.47 r0 top value=100k
R7 "RC0402JR-070RL" 0402S 428.07,1858 r0 top value=0
R8 "RC0402JR-070RL" 0402S 447.48,623.74 r0 top value=0
R9 "RC1005F2323CS" 0402#1 521,1877 r180 top value=232k
R10 "RC1005F2323CS" 0402#1 522.38,2028.76 r180 top value=232k
R11 "ERJ-2RKF1003X" 0402#1 535.46,574.47 r180 top value=100k
R12 "RC0402JR-070RL" 0402S 514.89,623.74 r180 top value=0
R13 "ERJPA2F1002X" 0402#1 644,2497 r0 top value=10.0k
R14 "ERA2AEB222X" 0402#1 631.34,2205.79 r90 top value=2.20k
R15 "ERJPA2F1002X" 0402#1 789,3082 r180 top value=10.0k
R16 "RC0201FR-07100KL" 0201 797,312.5 r0 top value=100k
R17 "RC0402JR-070RL" 0402S 832,1497.61 r0 top value=0
R18 "ERJPA2F1002X" 0402#1 855.81,3186.25 r180 top value=10.0k
R19 "ERJPA2F1002X" 0402#1 855.88,3239 r180 top value=10.0k
R20 "ERJPA2F1002X" 0402#1 856.19,3138.22 r180 top value=10.0k
R21 "RC0402JR-070RL" 0402S 874.19,3076.86 r0 top value=0
R22 "RC0201FR-07100KL" 0201 882.01,285.7 r180 top value=100k
R23 "RC0402JR-070RL" 0402S 894.19,3037.53 r0 top value=0
R24 "RC0402JR-070RL" 0402S 894.19,2996.53 r0 top value=0
R25 "RC0402FR-0749R9L" 0402#1 1014,826 r0 top value=49.9
R26 "RC0402FR-0749R9L" 0402#1 1014,776 r0 top value=49.9
R27 "RC0402FR-0749R9L" 0402#1 1017,1026.34 r0 top value=49.9
R28 "RC0402FR-0749R9L" 0402#1 1017,975.87 r0 top value=49.9
R29 "RC0402FR-0749R9L" 0402#1 1014,874.93 r0 top value=49.9
R30 "RC0402JR-070RL" 0402S 1017,1157.56 r0 top value=0
R31 "RC0402JR-070RL" 0402S 1017,1116 r0 top value=0
R32 "RC0402JR-070RL" 0402S 1017,1075 r0 top value=0
R33 "ERJPA2F1002X" 0402#1 1096.95,443.36 r180 top value=10.0k
R34 "ERJPA2F1002X" 0402#1 1074.95,517.44 r90 top value=10.0k
R35 "ERJ-2RKF1003X" 0402#1 1131,1026.05 r180 top value=100k
R36 "ERJ-2RKF1003X" 0402#1 1131,877.82 r180 top value=100k
R37 "ERJ-2RKF1003X" 0402#1 1131,925.23 r180 top value=100k
R38 "ERJ-2RKF1003X" 0402#1 1131,975.64 r180 top value=100k
R39 "ERJ-2RKF1003X" 0402#1 1131,830 r180 top value=100k
R40 "ERJ-2RKF1003X" 0402#1 1131,783 r180 top value=100k
R41 "Resistor" 0402#1 1157,1897 r180 top value=0
R42 "RMCF0603ZT0R00" 0603 1178.12,2191.59 r90 top value=0
R43 "ERJPA2F1002X" 0402#1 1261.62,546.15 r180 top value=10.0k
R44 "ERJPA2F1002X" 0402#1 1261.84,486.65 r180 top value=10.0k
R45 "RC0402JR-070RL" 0402S 1281,2384 r270 top value=0
R46 "RC0402JR-070RL" 0402S 1281,2316 r90 top value=0
R47 "RC0402JR-070RL" 0402S 1362.42,1974.84 r270 top value=0
R48 "RC0402JR-070RL" 0402S 1377.02,288 r90 top value=0
R49 "RC0402JR-070RL" 0402S 1425,1975 r270 top value=0
R50 "RC0402JR-070RL" 0402S 1483.78,288 r90 top value=0
R51 "RC0402JR-070RL" 0402S 1505,1958 r0 top value=0
R52 "RC0402JR-070RL" 0402S 1507,2014 r270 top value=0
R53 "RC0402JR-070RL" 0402S 1541.34,2014 r270 top value=0
R54 "RC0402JR-070RL" 0402S 1570,288 r90 top value=0
R55 "CRCW04021K00FKED" 0402#1 1659.11,1446.12 r180 top value=1.00k
R56 "CRCW04021K00FKED" 0402#1 1659.11,1358.12 r180 top value=1.00k
R57 "CRCW04021K00FKED" 0402#1 1659.29,1401.12 r180 top value=1.00k
R58 "RC0402JR-070RL" 0402S 1626.97,1974.84 r270 top value=0
R59 "RC0402JR-070RL" 0402S 1675,288 r90 top value=0
R60 "RC0402JR-070RL" 0402S 1725.14,1974.84 r270 top value=0
R61 "ERJ-2RKF2400X" 0402#1 1744,2177.35 r270 top value=240
R62 "CRCW060349R9FKEA" 0603 1812,3346 r180 top value=49.9
R63 "RMCF0402FT1M00" 0402#1 1815,2426 r270 top value=1.00Meg
R64 "CSRN2010FK40L0" 2010 1875,3073 r90 top value=0.04
R65 "RC0402JR-070RL" 0402S 1825.78,1713 r270 top value=0
R66 "RC0402JR-070RL" 0402S 1826.24,1974.84 r270 top value=0
R67 "RC0603FR-07324KL" 0603 1939,3348 r180 top value=324k
R68 "CRCW060328K7FKEA" 0603 1939,3241 r180 top value=28.7k
R69 "RC0402JR-070RL" 0402S 1925.78,288 r270 top value=0
R70 "RC0402JR-070RL" 0402S 1926,1974.84 r270 top value=0
R71 "RC0402JR-070RL" 0402S 1972.62,288 r90 top value=0
R72 "CRCW0603147KFKEA" 0603 2072.03,3255 r180 top value=147k
R73 "RC0402JR-070RL" 0402S 2025.59,288 r270 top value=0
R74 "RC0402JR-070RL" 0402S 2025.78,1974.84 r270 top value=0
R75 "RC0402JR-070RL" 0402S 2125,258 r270 top value=0
R76 "ERJ-2RKF4701X" 0402#1 2187,3260.54 r180 top value=4.70k
R77 "ERJPA2F1002X" 0402#1 2227.7,3373.7 r180 top value=10.0k
R78 "RC0402JR-070RL" 0402S 2207,3528.24 r180 top value=0
R79 "RC0402JR-070RL" 0402S 2207,3486 r0 top value=0
R80 "RC0402JR-070RL" 0402S 2208.81,3049.72 r180 top value=0
R81 "RC0402JR-070RL" 0402S 2208.81,3014.64 r180 top value=0
R82 "RC0402JR-070RL" 0402S 2208.81,2980.98 r180 top value=0
R83 "RC0402JR-070RL" 0402S 2208.81,2946.98 r180 top value=0
R84 "RC0402JR-070RL" 0402S 2224.03,258 r270 top value=0
R85 "ERJ-2RKF4701X" 0402#1 2264.15,3185.49 r90 top value=4.70k
R86 "RMCF0603ZT0R00" 0603 2279,3696 r270 bottom value=0
R87 "RMCF0603ZT0R00" 0603 2207.74,2088.89 r180 bottom value=0
R88 "RMCF0603ZT0R00" 0603 2207,3789 r180 bottom value=0
R89 "CRCW04021K00FKED" 0402#1 2152.03,1224 r0 bottom value=1.00k
R90 "RC0402JR-070RL" 0402S 2154,3577 r90 bottom value=0
R91 "RR1220P-104-D" 0805_HV 2094.44,2021.08 r270 bottom value=100k
R92 "ERJ-2BQFR33X" 0402#1 2080.41,2256 r0 bottom value=0.33
R93 "CRCW0402100KFKED" 0402#1 2025,2184 r270 bottom value=100k
R94 "CRCW0402475KFKED" 0402#1 2020,2074.14 r90 bottom value=475k
R95 "RMCF0603ZT0R00" 0603 1995.73,3779.79 r90 bottom value=0
R96 "RC0201FR-07100KL" 0201 1989.99,1373 r0 bottom value=100k
R97 "RC0201FR-07100KL" 0201 1989.01,1409 r0 bottom value=100k
R98 "RC0201FR-07100KL" 0201 1988.46,1444 r0 bottom value=100k
R99 "CRCW0402124KFKED" 0402#1 1978,2184.14 r90 bottom value=124k
R100 "RMCF0603ZT0R00" 0603 1935,2085.87 r0 bottom value=0
R101 "RMCF0603ZT0R00" 0603 1934.42,2030.84 r0 bottom value=0
R102 "ERJ-2BQFR33X" 0402#1 1936.37,879.2 r270 bottom value=0.33
R103 "ERJ-2BQFR33X" 0402#1 1901.05,1181 r180 bottom value=0.33
R104 "CRCW04021K00FKED" 0402#1 1864,2292.34 r0 bottom value=1.00k
R105 "CRCW04021K00FKED" 0402#1 1824,2075 r180 bottom value=1.00k
R106 "ERJ-2RKF2400X" 0402#1 1746,2261 r0 bottom value=240
R107 "CRCW0402100KFKED" 0402#1 1742.54,1392.69 r90 bottom value=100k
R108 "RMCF0603ZT0R00" 0603 1698.66,1049.12 r270 bottom value=0
R109 "RC0201FR-07511KL" 0201 1691.53,1370.75 r0 bottom value=511k
R110 "RC0603FR-0791KL" 0603 1650,1423 r0 bottom value=91.0k
R111 "ERJPA2F1002X" 0402#1 1624,2094 r180 bottom value=10.0k
R112 "RMCF0603ZT0R00" 0603 1638.45,1049.12 r270 bottom value=0
R113 "CRCW04021K00FKED" 0402#1 1610,2143 r180 bottom value=1.00k
R114 "CRCW060336K5FKEA" 0603 1577.54,1049.12 r270 bottom value=36.5k
R115 "RC0402JR-070RL" 0402S 1561,2207 r0 bottom value=0
R116 "RC0201FR-07100KL" 0201 1557.01,1384.69 r180 bottom value=100k
R117 "ERJPA2F1002X" 0402#1 1535,2121.3 r270 bottom value=10.0k
R118 "RC0201FR-07100KL" 0201 1531,1003.01 r90 bottom value=100k
R119 "RC0402JR-070RL" 0402S 1513,2230 r270 bottom value=0
R120 "ERJ-2RKF4701X" 0402#1 1490,2121 r90 bottom value=4.70k
R121 "RC0402FR-0749R9L" 0402#1 1429.13,1986 r180 bottom value=49.9
R122 "ERJPA2F1002X" 0402#1 1441,2120.82 r270 bottom value=10.0k
R123 "RMCF0603ZT0R00" 0603 1427,903 r270 bottom value=0
R124 "RL0603FR-070R02L" 0603 1410.17,1277.21 r270 bottom value=0.02
R125 "RC0402JR-070RL" 0402S 1387.4,2201.95 r0 bottom value=0
R126 "RC0402JR-070RL" 0402S 1345.58,2626.58 r180 bottom value=0
R127 "RG1005P-104-B-T5" 0402#1 1346.84,1028.85 r90 bottom value=100k
R128 "RG1005P-104-B-T5" 0402#1 1311.54,1165.6 r180 bottom value=100k
R129 "ERJPA2F1002X" 0402#1 1311.54,1123 r180 bottom value=10.0k
R130 "RC0402JR-070RL" 0402S 1333,2423 r270 bottom value=0
R131 "ERJPA2F1002X" 0402#1 1297.79,1028.85 r90 bottom value=10.0k
R132 "ERJPA2F1002X" 0402#1 1274.94,2365 r90 bottom value=10.0k
R133 "CRCW040210K0JNED" 0402#1 1093.59,1717.35 r180 bottom value=10k
R134 "RL0603FR-070R02L" 0603 1114,2338 r270 bottom value=0.02
R135 "RC0201FR-0782K5L" 0201 1094,2162 r0 bottom value=82.5k
R136 "RC0402JR-070RL" 0402S 1051.7,392 r0 bottom value=0
R137 "RR1220P-104-D" 0805_HV 1023,2101 r270 bottom value=100k
R138 "RC0402JR-070RL" 0402S 997.6,3968.93 r180 bottom value=0
R139 "RC0402JR-070RL" 0402S 997.6,3926 r180 bottom value=0
R140 "RC0402JR-070RL" 0402S 997,4011 r180 bottom value=0
R141 "CRCW0402100KFKED" 0402#1 933.38,2183 r0 bottom value=100k
R142 "CRCW040282K5FKED" 0402#1 933,2139 r180 bottom value=82.5k
R143 "RC0402JR-070RL" 0402S 959.7,3076.06 r270 bottom value=0
R144 "RC0402JR-070RL" 0402S 959.7,3005.2 r90 bottom value=0
R145 "ERJ-2BQFR33X" 0402#1 862,2929 r270 bottom value=0.33
R146 "ERJ-2BQFR33X" 0402#1 831,2349 r90 bottom value=0.33
R147 "CRCW0402200KFKED" 0402#1 788.72,3021.28 r0 bottom value=200k
R148 "CRCW0402100KFKED" 0402#1 788,2976 r180 bottom value=100k
R149 "RC0201FR-0782K5L" 0201 708.51,2971 r180 bottom value=82.5k
R150 "RL0603FR-070R02L" 0603 699.59,2797.29 r90 bottom value=0.02
R151 "RMCF0603ZT0R00" 0603 658.78,306 r180 bottom value=0
R152 "RR1220P-104-D" 0805_HV 622,2839 r270 bottom value=100k
R153 "RC0402JR-070RL" 0402S 599.25,3242.41 r0 bottom value=0
R154 "RC0402JR-070RL" 0402S 596.81,3324.01 r0 bottom value=0
R155 "RC0402JR-070RL" 0402S 605,697.92 r90 bottom value=0
R156 "RC0402JR-070RL" 0402S 553,697.2 r90 bottom value=0
R157 "RC0402JR-070RL" 0402S 467,3192 r180 bottom value=0
R158 "RC0402JR-070RL" 0402S 419,3442 r0 bottom value=0
R159 "RC0402JR-070RL" 0402S 394.86,790.65 r0 bottom value=0
R160 "RC0402JR-070RL" 0402S 394.22,754 r0 bottom value=0
R161 "ERJPA2F1002X" 0402#1 384.52,3165.45 r90 bottom value=10.0k
R162 "RC0402JR-070RL" 0402S 349.04,3799.21 r0 bottom value=0
R163 "RC0201FR-07100KL" 0201 308.01,3113.71 r0 bottom value=100k
R164 "RC0201FR-07100KL" 0201 308.01,2964.71 r0 bottom value=100k
R165 "RC0201FR-07100KL" 0201 308.01,2919.71 r0 bottom value=100k
R166 "RC0201FR-07100KL" 0201 308.01,2877.71 r0 bottom value=100k
R167 "RC0201FR-07100KL" 0201 308,3201 r0 bottom value=100k
R168 "RC0201FR-07100KL" 0201 308,3162 r0 bottom value=100k
R169 "RC0402JR-070RL" 0402S 281.76,3785.12 r180 bottom value=0
R170 "ERJPA2F1002X" 0402#1 267.38,3486.81 r90 bottom value=10.0k
R171 "RC0402JR-070RL" 0402S 257,3654 r0 bottom value=0
R172 "CRCW04021K00FKED" 0402#1 230.19,3321.35 r0 bottom value=1.00k
R173 "CRCW04021K00FKED" 0402#1 230.19,3272.35 r0 bottom value=1.00k
R174 "RC0402JR-070RL" 0402S 213,3785.12 r0 bottom value=0
R175 "RC0402JR-070RL" 0402S 203.09,1076.67 r0 bottom value=0
R176 "RC0402JR-070RL" 0402S 186.92,725.33 r180 bottom value=0
R177 "RC0402JR-070RL" 0402S 186.92,685.43 r180 bottom value=0
R178 "RC0402JR-070RL" 0402S 168,1638 r90 bottom value=0
R179 "RC0402JR-070RL" 0402S 152,2454 r270 bottom value=0
R180 "RC0402JR-070RL" 0402S 138,1795 r180 bottom value=0
R181 "RC0402JR-070RL" 0402S 141,2668 r270 bottom value=0
R182 "CRCW04021K00FKED" 0402#1 93.53,2517 r180 bottom value=1.00k
R183 "CRCW04021K00FKED" 0402#1 86.59,2447 r180 bottom value=1.00k
R184 "RC0402JR-070RL" 0402S 94.52,3115 r180 bottom value=0
R185 "CRCW04021K00FKED" 0402#1 65.96,1553.71 r0 bottom value=1.00k
R186 "CRCW04021K00FKED" 0402#1 46,1848 r90 bottom value=1.00k
R187 "ERJPA2F1002X" 0402#1 1131,1075 r0 top value=10.0k
REF "TP_SM_1MM" TP_SM_1MM 2104.82,3188.65 r180 top
RST "TP_SM_1MM" TP_SM_1MM 1419.35,2117 r90 top
SHDN "TP_SM_1MM" TP_SM_1MM 450,2147.39 r180 top
SID "TP_SM_1MM" TP_SM_1MM 1218,3277.47 r90 top
SW1 "430152070826" FP-430152070826_SMT_TACT-MFG 649.74,140.57 r0 top
SW2 "430152070826" FP-430152070826_SMT_TACT-MFG 1094,141 r0 top
SW3 "CVS-03TB" SW_CVS-03B 1869.69,1403.89 r0 top
SYSON1 "TP_SM_1MM" TP_SM_1MM 1043,2074 r270 top
SYSON2 "TP_SM_1MM" TP_SM_1MM 720.91,2977.5 r270 top
TP4 "Bias" Keystone5000 1757,3780 r90 top
U1 "CC3235MODASF12MONR" MON0063A 456.65,1051.67 r180 top locked
U2 "TPA2011D1YFFR" YFF0009AAAC 428.07,1953.93 r180 top
U3 "LM66100DCKT" DCK0006A_N 620.43,3603.29 r90 top
U4 "TPS22919DCKT" DCK0006A_N 762.29,2575.79 r0 top
U5 "LM66100DCKT" DCK0006A_N 928.88,3655.17 r180 top
U6 "OPT3004DNPR" DNP0006A 1156.57,518.15 r0 top
U7 "TPS7A0325PDQNR" DQN0004A-MFG 1150.2,2025.43 r270 top
U8 "TPD2E001DRLR" DRL0005A 1359.95,3877.5 r0 top
U9 "TLV61048DBVR" DBV0006A_N 2082,3424 r0 top
U10 "TPS22919DCKT" DCK0006A_N 2098,3655.17 r180 bottom
U11 "TPS62821DLCR" DLC0008A 2090.26,2167.5 r0 bottom
U12 "TPS63802DLAT" DLA0010A 1624.17,1284.21 r270 bottom
U13 "TPS63900DSK" DSK0010A 1619,908.87 r270 bottom
U14 "TPS62825DMQR" DMQ0006A 1022.79,2220.8 r90 bottom
U15 "DRV8837CDSG" DSG0008A 905,3962.97 r0 bottom
U16 "TPS62821DLCR" DLC0008A 778.2,2914.77 r270 bottom
U17 "MX25U12835FZNI-10G‎" "Winbond-WSON6x5_Code P" 459.52,2956.44 r270 bottom locked
U18 "TLV2761CD" D0008A_N 418.72,3317.89 r0 bottom
U19 "TPS22919DCKT" DCK0006A_N 226,3718.28 r180 bottom
U20 "TPS22919DCKT" DCK0006A_N 97.78,3300.76 r0 bottom
U21 "TPD4E101DPWR" DPW0004A#1 92,3162 r180 bottom
U22 "TPD4E101DPWR" DPW0004A#2 82.88,2885.99 r180 bottom
USB "TP_SM_1MM" TP_SM_1MM 1177.77,3622.54 r0 top
VBAT "RCU-0C" TE_RCU 727.07,3693 r90 top
VCC_ALS "TP_SM_1MM" TP_SM_1MM 1149.95,686.44 r180 top
VCC_AMP "TP_SM_1MM" TP_SM_1MM 103,3770 r180 top
VCC_IR "TP_SM_1MM" TP_SM_1MM 941,3849 r90 top
VCC_MEM "TP_SM_1MM" TP_SM_1MM 1572.29,1446.12 r0 top
VDDAO "TP_SM_1MM" TP_SM_1MM 1337.44,2695.06 r0 top
VeFuse "TP_SM_1MM" TP_SM_1MM 1037.58,2336.15 r90 top
VMID "TP_SM_1MM" TP_SM_1MM 1137,2666 r270 top
VOUT1 "TP_SM_1MM" TP_SM_1MM 1888.26,1224.28 r270 top
VOUT2 "TP_SM_1MM" TP_SM_1MM 1786.96,780 r180 top
VP "TP_SM_1MM" TP_SM_1MM 2279,3487.45 r0 top
VREF "TP_SM_1MM" TP_SM_1MM 2051,2285.51 r180 top
VREF_AU "TP_SM_1MM" TP_SM_1MM 962.44,2336.15 r90 top
Y1 "‎8Q-24.000MEEV-T‎" FP-8Q-24.000MEIV-T_SMD-4-MFG 1754.11,2423 r270 top
ZZ1 "These assemblies are ESD sensitive, ESD precautions shall be observed." AssemblyNote 27.82,4619.38 r0 top
ZZ2 "These assemblies must be clean and free from flux and all contaminants. Use of no clean flux is not acceptable." AssemblyNote 27.82,4530.83 r0 top
ZZ3 "These assemblies must comply with workmanship standards IPC-A-610 Class 2, unless otherwise specified." AssemblyNote 27.82,4442.27 r0 top
ZZ4 "This Assembly Note is for PCB labels only" AssemblyNoteLabel 29.62,4776.35 r0 top

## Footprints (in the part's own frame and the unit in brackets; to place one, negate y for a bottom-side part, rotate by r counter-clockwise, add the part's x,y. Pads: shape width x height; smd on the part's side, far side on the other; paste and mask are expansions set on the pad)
3M_951204-8622 [mm] "Header, 2mm, 2x2, TH"
  rrect50% 1.3x1.3 hole 0.8: 1(-1,1)
  round 1.3 hole 0.8: 2(1,1) 3(-1,-1) 4(1,-1)
  silkscreen extent -2.4,-2 2,2, body extent -2,-2 2,2, height 5.9
0201 [mm] "Data from Kemet datasheet CC101_COM dated 7/28/11"
  rect 0.46x0.42 smd mask+0.048: 1(-0.33,0) 2(0.33,0)
  body extent -0.31,-0.16 0.31,0.16, height 0.26
0402#1 [mm] "0402 from SM-752 data"
  rect 0.8x0.6 smd: 1(-0.6,0) 2(0.6,0)
  silkscreen extent -1.22,-0.52 1.22,0.52, body extent -0.55,-0.3 0.55,0.3, height 0.6
0402#2 [mm] "Chip Capacitor, Body 1.0x0.5mm, IPC High Density"
  rect 0.6x0.5 smd: 1(-0.5,0) 2(0.5,0)
  body extent -0.55,-0.3 0.55,0.3, height 1.3
0402_065 [mm] "0402"
  rect 0.8x0.6 smd: 1(-0.6,0) 2(0.6,0)
  silkscreen extent -1.22,-0.52 1.22,0.52, body extent -0.55,-0.3 0.55,0.3, height 0.65
0402_070 [mil] "SMD, 2-Leads, Body 1.2x0.7mm, Height 0.7mm"
  rect 15x24 smd: 1(-20,0) 2(20,0)
  body extent -24,-14 24,14, height 28
0402S [mil] "Based on C0402S footprint from PADS legacy"
  rect 15x24 smd: 1(-20,0) 2(20,0)
  body extent -22,-12 22,12, height 24
0603 [mm] "0603 from SM-752 data"
  rect 1x0.95 smd: 1(-0.8,0) 2(0.8,0)
  silkscreen extent -1.52,-0.69 1.52,0.69, body extent -0.87,-0.47 0.87,0.47, height 1
0805_HV [mil] "0805 with 30mil clearance between pads"
  rect 50x63 smd: 1(-40,0) 2(40,0)
  silkscreen extent -74,-40 74,40, body extent -43,-29 43,29, height 57
1210_270 [mm] "1210"
  rect 1.3x2.7 smd: 1(-1.45,0) 2(1.45,0)
  silkscreen extent -2.32,-1.57 2.32,1.57, body extent -1.7,-1.35 1.7,1.35, height 2.7
1210_280 [mm] "SMD, 2-Leads, Body 3.6x2.8mm, Height 2.8mm"
  rect 1.1x2.2 smd: 1(-1.65,0) 2(1.65,0)
  silkscreen extent -0.84,-1.4 0.84,1.4, body extent -1.8,-1.4 1.8,1.4, height 2.8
